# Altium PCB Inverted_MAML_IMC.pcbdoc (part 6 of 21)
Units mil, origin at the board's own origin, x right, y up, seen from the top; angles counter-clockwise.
Board outline 7677.1 x 6771.6 mil, 6 copper layers (Top Layer, Inner1, Inner2, Inner3, Inner4, Bottom Layer), stack 60.7 mil thick; 2732 components, 1531 nets, 7765 pads, 3705 vias.
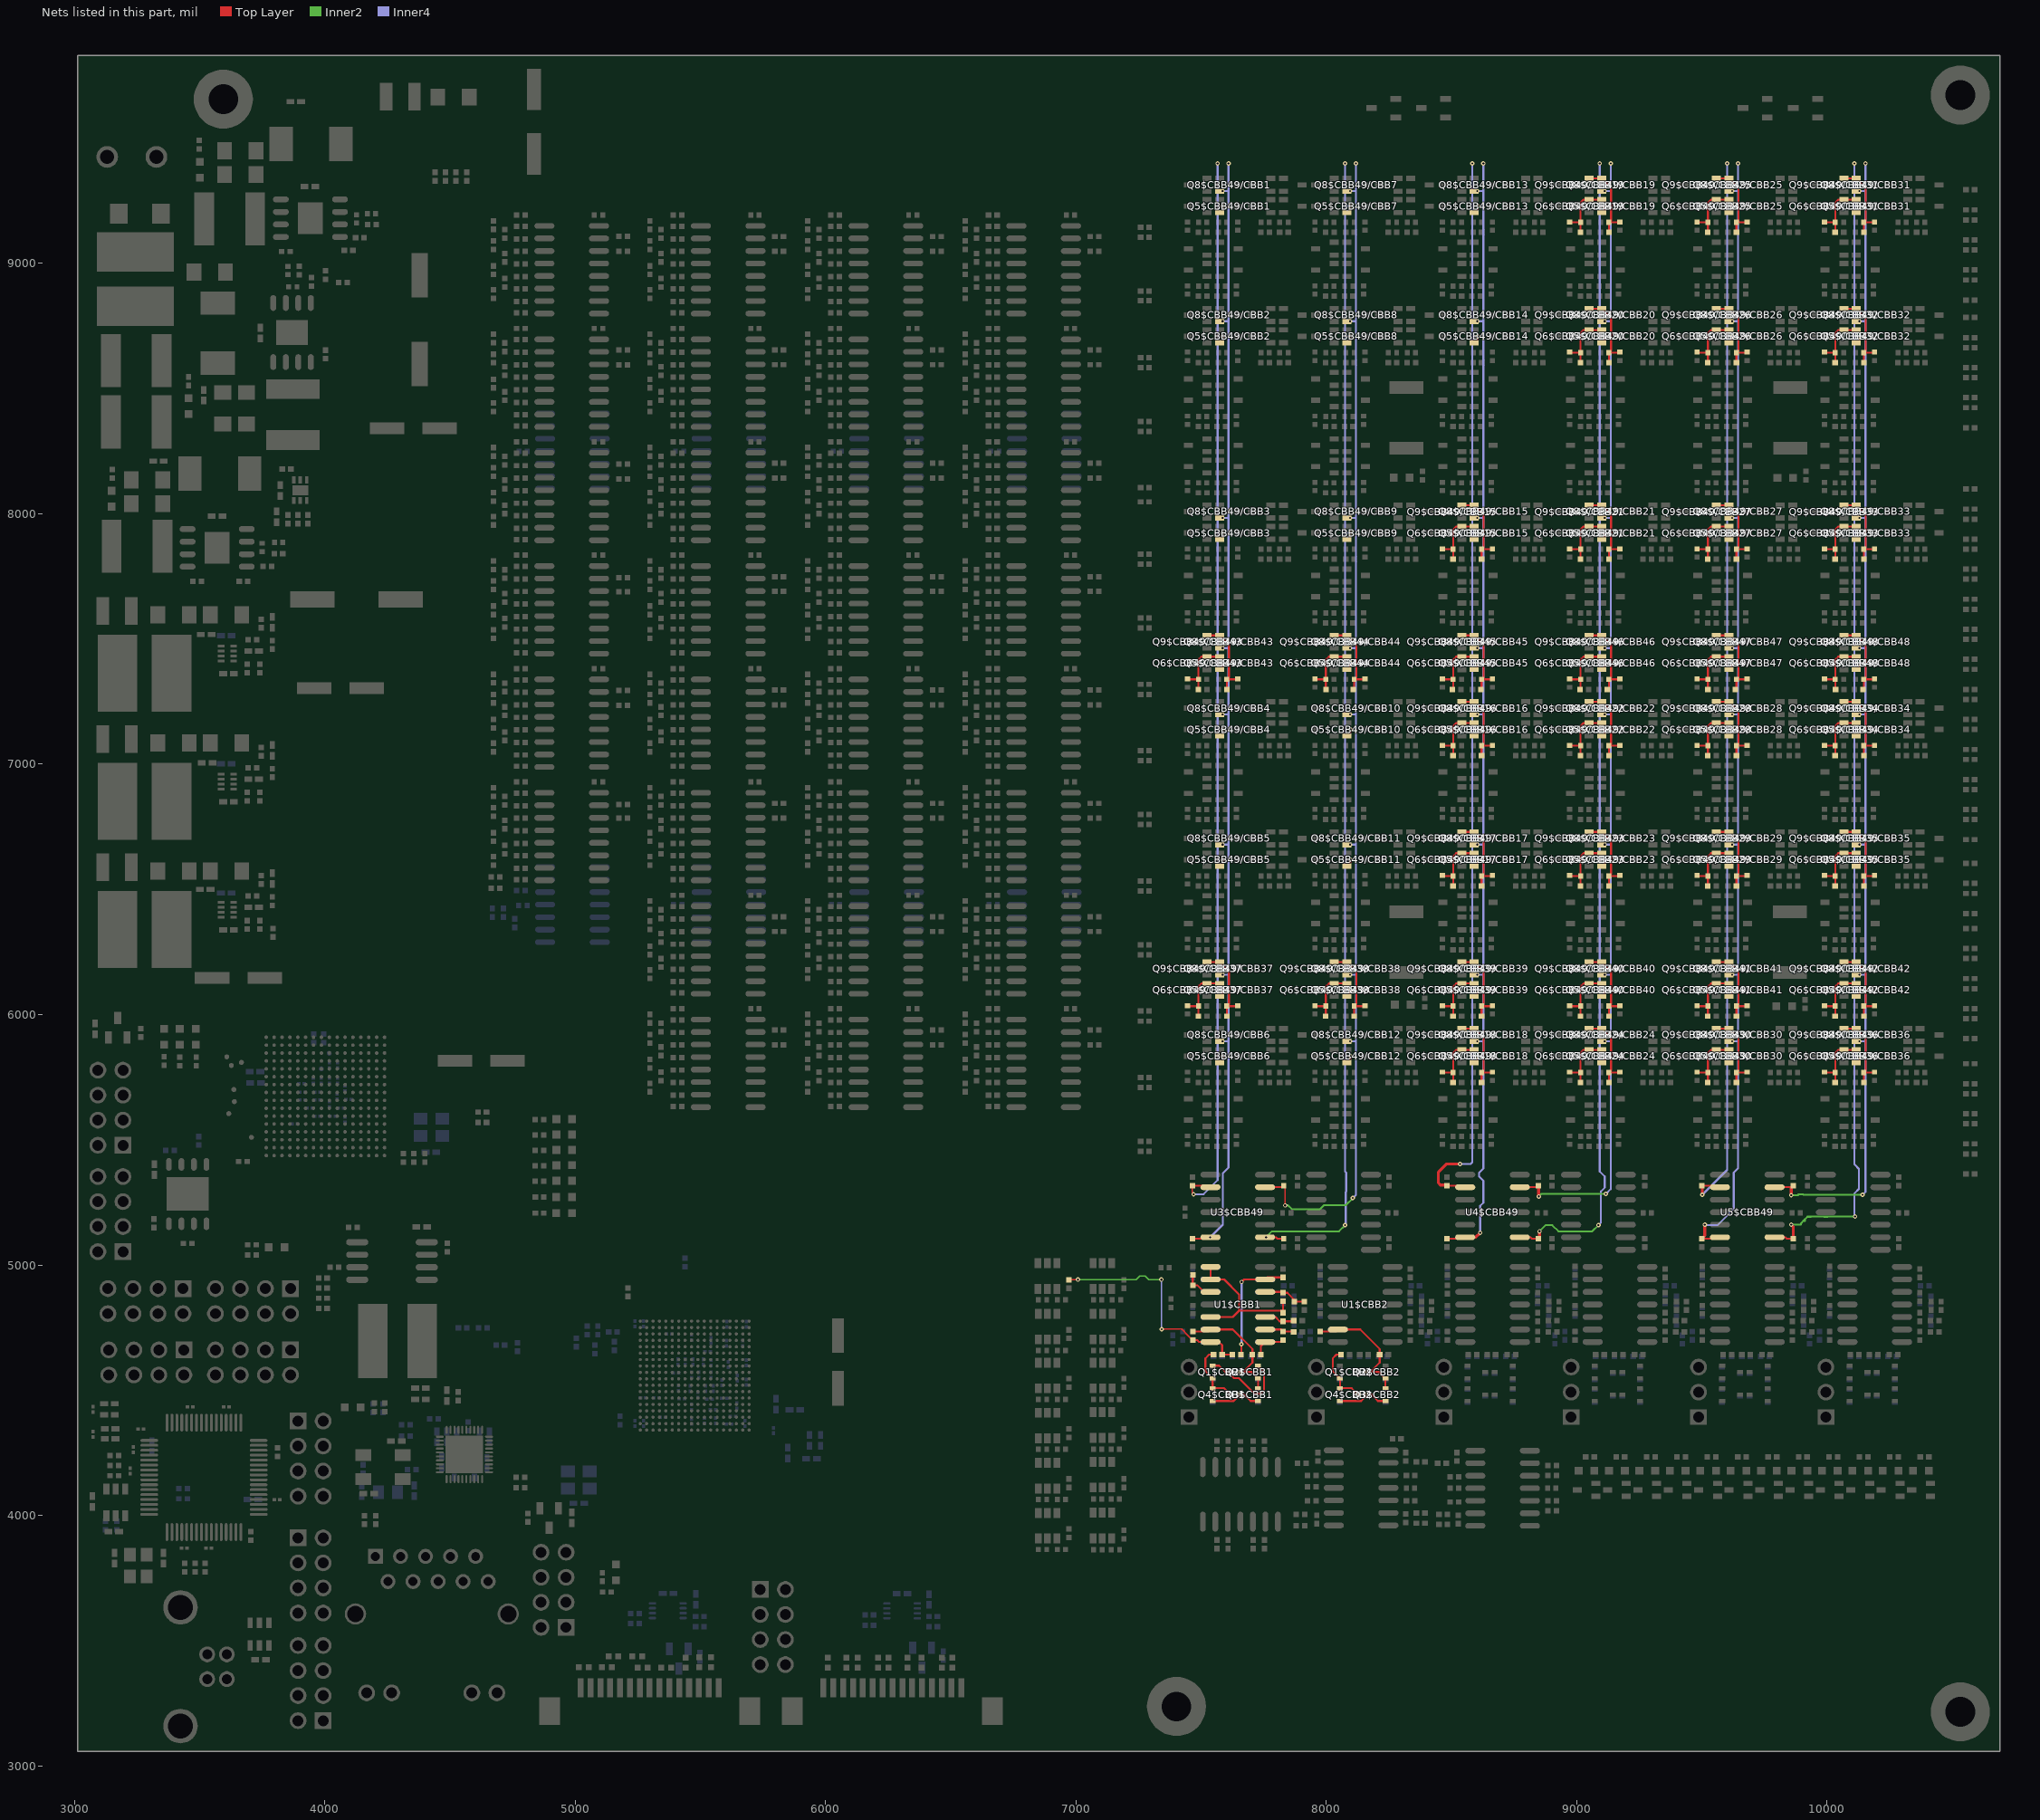
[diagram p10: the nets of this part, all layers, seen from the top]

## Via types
v1: diameter 17.7, hole 7.9, Top Layer to Bottom Layer, 3373 vias
v2: diameter 13.8, hole 7.9, Top Layer to Bottom Layer, 287 vias
v3: diameter 23.6, hole 11.8, Top Layer to Bottom Layer, 45 vias

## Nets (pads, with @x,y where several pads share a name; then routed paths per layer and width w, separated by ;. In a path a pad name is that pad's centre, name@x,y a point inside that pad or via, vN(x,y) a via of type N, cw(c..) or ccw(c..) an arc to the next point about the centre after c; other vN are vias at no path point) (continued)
$1I15\$1I16\$2N1: C1$CBB49/CBB15.2 C2$CBB49/CBB15.2 Q5$CBB49/CBB15.1 Q6$CBB49/CBB15.2 R1$CBB49/CBB15.2 | length 251.9
  Top Layer w7.9: C2$CBB49/CBB15.2@8463.6,7860.2 8465.1,7858.7 C1$CBB49/CBB15.2@8507,7858.7 ; R1$CBB49/CBB15.2@8506.5,7818.7 8507,7819.2 C1$CBB49/CBB15.2@8507,7858.7 ; Q5$CBB49/CBB15.1@8591.2,7949.3 Q6$CBB49/CBB15.2@8541,7949.3 8519.2,7949.3 8507,7937.2 C1$CBB49/CBB15.2@8507,7858.7
$1I15\$1I16\$2N14: C3$CBB49/CBB15.2 C4$CBB49/CBB15.2 Q8$CBB49/CBB15.1 Q9$CBB49/CBB15.2 R2$CBB49/CBB15.2 | length 329.1
  Top Layer w7.9: Q9$CBB49/CBB15.2@8541,8034.3 Q8$CBB49/CBB15.1@8591.2,8034.3 8628.6,7996.9 8628.6,7867.2 C3$CBB49/CBB15.2@8620.1,7858.7 ; R2$CBB49/CBB15.2@8620.6,7818.7 8620.6,7858.2 C3$CBB49/CBB15.2@8620.1,7858.7 ; C4$CBB49/CBB15.2@8663.6,7860.2 8662,7858.7 C3$CBB49/CBB15.2@8620.1,7858.7
$1I15\$1I17\$2N1: C1$CBB49/CBB16.2 C2$CBB49/CBB16.2 Q5$CBB49/CBB16.1 Q6$CBB49/CBB16.2 R1$CBB49/CBB16.2 | length 251.9
  Top Layer w7.9: C2$CBB49/CBB16.2@8463.6,7075.2 8465.1,7073.7 C1$CBB49/CBB16.2@8507,7073.7 ; R1$CBB49/CBB16.2@8506.5,7033.7 8507,7034.2 C1$CBB49/CBB16.2@8507,7073.7 ; Q5$CBB49/CBB16.1@8591.2,7164.3 Q6$CBB49/CBB16.2@8541,7164.3 8519.2,7164.3 8507,7152.2 C1$CBB49/CBB16.2@8507,7073.7
$1I15\$1I17\$2N14: C3$CBB49/CBB16.2 C4$CBB49/CBB16.2 Q8$CBB49/CBB16.1 Q9$CBB49/CBB16.2 R2$CBB49/CBB16.2 | length 329.1
  Top Layer w7.9: Q9$CBB49/CBB16.2@8541,7249.3 Q8$CBB49/CBB16.1@8591.2,7249.3 8628.6,7211.9 8628.6,7082.2 C3$CBB49/CBB16.2@8620.1,7073.7 ; R2$CBB49/CBB16.2@8620.6,7033.7 8620.6,7073.2 C3$CBB49/CBB16.2@8620.1,7073.7 ; C4$CBB49/CBB16.2@8663.6,7075.2 8662,7073.7 C3$CBB49/CBB16.2@8620.1,7073.7
$1I15\$1I18\$2N1: C1$CBB49/CBB17.2 C2$CBB49/CBB17.2 Q5$CBB49/CBB17.1 Q6$CBB49/CBB17.2 R1$CBB49/CBB17.2 | length 251.9
  Top Layer w7.9: C2$CBB49/CBB17.2@8463.6,6555.2 8465.1,6553.7 C1$CBB49/CBB17.2@8507,6553.7 ; R1$CBB49/CBB17.2@8506.5,6513.7 8507,6514.2 C1$CBB49/CBB17.2@8507,6553.7 ; Q5$CBB49/CBB17.1@8591.2,6644.3 Q6$CBB49/CBB17.2@8541,6644.3 8519.2,6644.3 8507,6632.2 C1$CBB49/CBB17.2@8507,6553.7
$1I15\$1I18\$2N14: C3$CBB49/CBB17.2 C4$CBB49/CBB17.2 Q8$CBB49/CBB17.1 Q9$CBB49/CBB17.2 R2$CBB49/CBB17.2 | length 329.1
  Top Layer w7.9: Q9$CBB49/CBB17.2@8541,6729.3 Q8$CBB49/CBB17.1@8591.2,6729.3 8628.6,6691.9 8628.6,6562.2 C3$CBB49/CBB17.2@8620.1,6553.7 ; R2$CBB49/CBB17.2@8620.6,6513.7 8620.6,6553.2 C3$CBB49/CBB17.2@8620.1,6553.7 ; C4$CBB49/CBB17.2@8663.6,6555.2 8662,6553.7 C3$CBB49/CBB17.2@8620.1,6553.7
$1I15\$1I19\$2N1: C1$CBB49/CBB18.2 C2$CBB49/CBB18.2 Q5$CBB49/CBB18.1 Q6$CBB49/CBB18.2 R1$CBB49/CBB18.2 | length 251.9
  Top Layer w7.9: C2$CBB49/CBB18.2@8463.6,5770.2 8465.1,5768.7 C1$CBB49/CBB18.2@8507,5768.7 ; R1$CBB49/CBB18.2@8506.5,5728.7 8507,5729.2 C1$CBB49/CBB18.2@8507,5768.7 ; Q5$CBB49/CBB18.1@8591.2,5859.3 Q6$CBB49/CBB18.2@8541,5859.3 8519.2,5859.3 8507,5847.2 C1$CBB49/CBB18.2@8507,5768.7
$1I15\$1I19\$2N14: C3$CBB49/CBB18.2 C4$CBB49/CBB18.2 Q8$CBB49/CBB18.1 Q9$CBB49/CBB18.2 R2$CBB49/CBB18.2 | length 329.1
  Top Layer w7.9: Q9$CBB49/CBB18.2@8541,5944.3 Q8$CBB49/CBB18.1@8591.2,5944.3 8628.6,5906.9 8628.6,5777.2 C3$CBB49/CBB18.2@8620.1,5768.7 ; R2$CBB49/CBB18.2@8620.6,5728.7 8620.6,5768.2 C3$CBB49/CBB18.2@8620.1,5768.7 ; C4$CBB49/CBB18.2@8663.6,5770.2 8662,5768.7 C3$CBB49/CBB18.2@8620.1,5768.7
$1I15\$1I20\$2N1: C1$CBB49/CBB19.2 C2$CBB49/CBB19.2 Q5$CBB49/CBB19.1 Q6$CBB49/CBB19.2 R1$CBB49/CBB19.2 | length 252
  Top Layer w7.9: C2$CBB49/CBB19.2@8972.3,9165.3 8973.8,9163.7 C1$CBB49/CBB19.2@9015.7,9163.7 ; R1$CBB49/CBB19.2@9015.2,9123.7 9015.7,9124.2 C1$CBB49/CBB19.2@9015.7,9163.7 ; Q5$CBB49/CBB19.1@9099.9,9254.3 Q6$CBB49/CBB19.2@9049.7,9254.3 9027.9,9254.3 9015.7,9242.2 C1$CBB49/CBB19.2@9015.7,9163.7
$1I15\$1I20\$2N14: C3$CBB49/CBB19.2 C4$CBB49/CBB19.2 Q8$CBB49/CBB19.1 Q9$CBB49/CBB19.2 R2$CBB49/CBB19.2 | length 329.2
  Top Layer w7.9: Q9$CBB49/CBB19.2@9049.7,9339.3 Q8$CBB49/CBB19.1@9099.9,9339.3 9137.3,9301.9 9137.3,9172.2 C3$CBB49/CBB19.2@9128.8,9163.7 ; R2$CBB49/CBB19.2@9129.3,9123.7 9129.3,9163.2 C3$CBB49/CBB19.2@9128.8,9163.7 ; C4$CBB49/CBB19.2@9172.3,9165.3 9170.7,9163.7 C3$CBB49/CBB19.2@9128.8,9163.7
$1I15\$1I21\$2N1: C1$CBB49/CBB20.2 C2$CBB49/CBB20.2 Q5$CBB49/CBB20.1 Q6$CBB49/CBB20.2 R1$CBB49/CBB20.2 | length 252
  Top Layer w7.9: C2$CBB49/CBB20.2@8972.3,8645.3 8973.8,8643.7 C1$CBB49/CBB20.2@9015.7,8643.7 ; R1$CBB49/CBB20.2@9015.2,8603.7 9015.7,8604.2 C1$CBB49/CBB20.2@9015.7,8643.7 ; Q5$CBB49/CBB20.1@9099.9,8734.3 Q6$CBB49/CBB20.2@9049.7,8734.3 9027.9,8734.3 9015.7,8722.2 C1$CBB49/CBB20.2@9015.7,8643.7
$1I15\$1I21\$2N14: C3$CBB49/CBB20.2 C4$CBB49/CBB20.2 Q8$CBB49/CBB20.1 Q9$CBB49/CBB20.2 R2$CBB49/CBB20.2 | length 329.2
  Top Layer w7.9: Q9$CBB49/CBB20.2@9049.7,8819.3 Q8$CBB49/CBB20.1@9099.9,8819.3 9137.3,8781.9 9137.3,8652.2 C3$CBB49/CBB20.2@9128.8,8643.7 ; R2$CBB49/CBB20.2@9129.3,8603.7 9129.3,8643.2 C3$CBB49/CBB20.2@9128.8,8643.7 ; C4$CBB49/CBB20.2@9172.3,8645.3 9170.7,8643.7 C3$CBB49/CBB20.2@9128.8,8643.7
$1I15\$1I22\$2N1: C1$CBB49/CBB21.2 C2$CBB49/CBB21.2 Q5$CBB49/CBB21.1 Q6$CBB49/CBB21.2 R1$CBB49/CBB21.2 | length 252
  Top Layer w7.9: C2$CBB49/CBB21.2@8972.3,7860.3 8973.8,7858.7 C1$CBB49/CBB21.2@9015.7,7858.7 ; R1$CBB49/CBB21.2@9015.2,7818.7 9015.7,7819.2 C1$CBB49/CBB21.2@9015.7,7858.7 ; Q5$CBB49/CBB21.1@9099.9,7949.3 Q6$CBB49/CBB21.2@9049.7,7949.3 9027.9,7949.3 9015.7,7937.2 C1$CBB49/CBB21.2@9015.7,7858.7
$1I15\$1I22\$2N14: C3$CBB49/CBB21.2 C4$CBB49/CBB21.2 Q8$CBB49/CBB21.1 Q9$CBB49/CBB21.2 R2$CBB49/CBB21.2 | length 329.2
  Top Layer w7.9: Q9$CBB49/CBB21.2@9049.7,8034.3 Q8$CBB49/CBB21.1@9099.9,8034.3 9137.3,7996.9 9137.3,7867.2 C3$CBB49/CBB21.2@9128.8,7858.7 ; R2$CBB49/CBB21.2@9129.3,7818.7 9129.3,7858.2 C3$CBB49/CBB21.2@9128.8,7858.7 ; C4$CBB49/CBB21.2@9172.3,7860.3 9170.7,7858.7 C3$CBB49/CBB21.2@9128.8,7858.7
$1I15\$1I23\$2N1: C1$CBB49/CBB22.2 C2$CBB49/CBB22.2 Q5$CBB49/CBB22.1 Q6$CBB49/CBB22.2 R1$CBB49/CBB22.2 | length 252
  Top Layer w7.9: C2$CBB49/CBB22.2@8972.3,7075.3 8973.8,7073.7 C1$CBB49/CBB22.2@9015.7,7073.7 ; R1$CBB49/CBB22.2@9015.2,7033.7 9015.7,7034.2 C1$CBB49/CBB22.2@9015.7,7073.7 ; Q5$CBB49/CBB22.1@9099.9,7164.3 Q6$CBB49/CBB22.2@9049.7,7164.3 9027.9,7164.3 9015.7,7152.2 C1$CBB49/CBB22.2@9015.7,7073.7
$1I15\$1I23\$2N14: C3$CBB49/CBB22.2 C4$CBB49/CBB22.2 Q8$CBB49/CBB22.1 Q9$CBB49/CBB22.2 R2$CBB49/CBB22.2 | length 329.2
  Top Layer w7.9: Q9$CBB49/CBB22.2@9049.7,7249.3 Q8$CBB49/CBB22.1@9099.9,7249.3 9137.3,7211.9 9137.3,7082.2 C3$CBB49/CBB22.2@9128.8,7073.7 ; R2$CBB49/CBB22.2@9129.3,7033.7 9129.3,7073.2 C3$CBB49/CBB22.2@9128.8,7073.7 ; C4$CBB49/CBB22.2@9172.3,7075.3 9170.7,7073.7 C3$CBB49/CBB22.2@9128.8,7073.7
$1I15\$1I24\$2N1: C1$CBB49/CBB23.2 C2$CBB49/CBB23.2 Q5$CBB49/CBB23.1 Q6$CBB49/CBB23.2 R1$CBB49/CBB23.2 | length 252
  Top Layer w7.9: C2$CBB49/CBB23.2@8972.3,6555.3 8973.8,6553.7 C1$CBB49/CBB23.2@9015.7,6553.7 ; R1$CBB49/CBB23.2@9015.2,6513.7 9015.7,6514.2 C1$CBB49/CBB23.2@9015.7,6553.7 ; Q5$CBB49/CBB23.1@9099.9,6644.3 Q6$CBB49/CBB23.2@9049.7,6644.3 9027.9,6644.3 9015.7,6632.2 C1$CBB49/CBB23.2@9015.7,6553.7
$1I15\$1I24\$2N14: C3$CBB49/CBB23.2 C4$CBB49/CBB23.2 Q8$CBB49/CBB23.1 Q9$CBB49/CBB23.2 R2$CBB49/CBB23.2 | length 329.2
  Top Layer w7.9: Q9$CBB49/CBB23.2@9049.7,6729.3 Q8$CBB49/CBB23.1@9099.9,6729.3 9137.3,6691.9 9137.3,6562.2 C3$CBB49/CBB23.2@9128.8,6553.7 ; R2$CBB49/CBB23.2@9129.3,6513.7 9129.3,6553.2 C3$CBB49/CBB23.2@9128.8,6553.7 ; C4$CBB49/CBB23.2@9172.3,6555.3 9170.7,6553.7 C3$CBB49/CBB23.2@9128.8,6553.7
$1I15\$1I25\$2N1: C1$CBB49/CBB24.2 C2$CBB49/CBB24.2 Q5$CBB49/CBB24.1 Q6$CBB49/CBB24.2 R1$CBB49/CBB24.2 | length 252
  Top Layer w7.9: C2$CBB49/CBB24.2@8972.3,5770.3 8973.8,5768.7 C1$CBB49/CBB24.2@9015.7,5768.7 ; R1$CBB49/CBB24.2@9015.2,5728.7 9015.7,5729.2 C1$CBB49/CBB24.2@9015.7,5768.7 ; Q5$CBB49/CBB24.1@9099.9,5859.3 Q6$CBB49/CBB24.2@9049.7,5859.3 9027.9,5859.3 9015.7,5847.2 C1$CBB49/CBB24.2@9015.7,5768.7
$1I15\$1I25\$2N14: C3$CBB49/CBB24.2 C4$CBB49/CBB24.2 Q8$CBB49/CBB24.1 Q9$CBB49/CBB24.2 R2$CBB49/CBB24.2 | length 329.2
  Top Layer w7.9: Q9$CBB49/CBB24.2@9049.7,5944.3 Q8$CBB49/CBB24.1@9099.9,5944.3 9137.3,5906.9 9137.3,5777.2 C3$CBB49/CBB24.2@9128.8,5768.7 ; R2$CBB49/CBB24.2@9129.3,5728.7 9129.3,5768.2 C3$CBB49/CBB24.2@9128.8,5768.7 ; C4$CBB49/CBB24.2@9172.3,5770.3 9170.7,5768.7 C3$CBB49/CBB24.2@9128.8,5768.7
$1I15\$1I26\$2N1: C1$CBB49/CBB25.2 C2$CBB49/CBB25.2 Q5$CBB49/CBB25.1 Q6$CBB49/CBB25.2 R1$CBB49/CBB25.2 | length 252
  Top Layer w7.9: C2$CBB49/CBB25.2@9481,9165.3 9482.5,9163.7 C1$CBB49/CBB25.2@9524.4,9163.7 ; R1$CBB49/CBB25.2@9523.9,9123.7 9524.4,9124.2 C1$CBB49/CBB25.2@9524.4,9163.7 ; Q5$CBB49/CBB25.1@9608.6,9254.3 Q6$CBB49/CBB25.2@9558.4,9254.3 9536.6,9254.3 9524.4,9242.2 C1$CBB49/CBB25.2@9524.4,9163.7
$1I15\$1I26\$2N14: C3$CBB49/CBB25.2 C4$CBB49/CBB25.2 Q8$CBB49/CBB25.1 Q9$CBB49/CBB25.2 R2$CBB49/CBB25.2 | length 329.2
  Top Layer w7.9: Q9$CBB49/CBB25.2@9558.4,9339.3 Q8$CBB49/CBB25.1@9608.6,9339.3 9646,9301.9 9646,9172.2 C3$CBB49/CBB25.2@9637.5,9163.7 ; R2$CBB49/CBB25.2@9638,9123.7 9638,9163.2 C3$CBB49/CBB25.2@9637.5,9163.7 ; C4$CBB49/CBB25.2@9681,9165.3 9679.4,9163.7 C3$CBB49/CBB25.2@9637.5,9163.7
$1I15\$1I27\$2N1: C1$CBB49/CBB26.2 C2$CBB49/CBB26.2 Q5$CBB49/CBB26.1 Q6$CBB49/CBB26.2 R1$CBB49/CBB26.2 | length 252
  Top Layer w7.9: C2$CBB49/CBB26.2@9481,8645.3 9482.5,8643.7 C1$CBB49/CBB26.2@9524.4,8643.7 ; R1$CBB49/CBB26.2@9523.9,8603.7 9524.4,8604.2 C1$CBB49/CBB26.2@9524.4,8643.7 ; Q5$CBB49/CBB26.1@9608.6,8734.3 Q6$CBB49/CBB26.2@9558.4,8734.3 9536.6,8734.3 9524.4,8722.2 C1$CBB49/CBB26.2@9524.4,8643.7
$1I15\$1I27\$2N14: C3$CBB49/CBB26.2 C4$CBB49/CBB26.2 Q8$CBB49/CBB26.1 Q9$CBB49/CBB26.2 R2$CBB49/CBB26.2 | length 329.2
  Top Layer w7.9: Q9$CBB49/CBB26.2@9558.4,8819.3 Q8$CBB49/CBB26.1@9608.6,8819.3 9646,8781.9 9646,8652.2 C3$CBB49/CBB26.2@9637.5,8643.7 ; R2$CBB49/CBB26.2@9638,8603.7 9638,8643.2 C3$CBB49/CBB26.2@9637.5,8643.7 ; C4$CBB49/CBB26.2@9681,8645.3 9679.4,8643.7 C3$CBB49/CBB26.2@9637.5,8643.7
$1I15\$1I28\$2N1: C1$CBB49/CBB27.2 C2$CBB49/CBB27.2 Q5$CBB49/CBB27.1 Q6$CBB49/CBB27.2 R1$CBB49/CBB27.2 | length 252
  Top Layer w7.9: C2$CBB49/CBB27.2@9481,7860.3 9482.5,7858.7 C1$CBB49/CBB27.2@9524.4,7858.7 ; R1$CBB49/CBB27.2@9523.9,7818.7 9524.4,7819.2 C1$CBB49/CBB27.2@9524.4,7858.7 ; Q5$CBB49/CBB27.1@9608.6,7949.3 Q6$CBB49/CBB27.2@9558.4,7949.3 9536.6,7949.3 9524.4,7937.2 C1$CBB49/CBB27.2@9524.4,7858.7
$1I15\$1I28\$2N14: C3$CBB49/CBB27.2 C4$CBB49/CBB27.2 Q8$CBB49/CBB27.1 Q9$CBB49/CBB27.2 R2$CBB49/CBB27.2 | length 329.2
  Top Layer w7.9: Q9$CBB49/CBB27.2@9558.4,8034.3 Q8$CBB49/CBB27.1@9608.6,8034.3 9646,7996.9 9646,7867.2 C3$CBB49/CBB27.2@9637.5,7858.7 ; R2$CBB49/CBB27.2@9638,7818.7 9638,7858.2 C3$CBB49/CBB27.2@9637.5,7858.7 ; C4$CBB49/CBB27.2@9681,7860.3 9679.4,7858.7 C3$CBB49/CBB27.2@9637.5,7858.7
$1I15\$1I29\$2N1: C1$CBB49/CBB28.2 C2$CBB49/CBB28.2 Q5$CBB49/CBB28.1 Q6$CBB49/CBB28.2 R1$CBB49/CBB28.2 | length 252
  Top Layer w7.9: C2$CBB49/CBB28.2@9481,7075.3 9482.5,7073.7 C1$CBB49/CBB28.2@9524.4,7073.7 ; R1$CBB49/CBB28.2@9523.9,7033.7 9524.4,7034.2 C1$CBB49/CBB28.2@9524.4,7073.7 ; Q5$CBB49/CBB28.1@9608.6,7164.3 Q6$CBB49/CBB28.2@9558.4,7164.3 9536.6,7164.3 9524.4,7152.2 C1$CBB49/CBB28.2@9524.4,7073.7
$1I15\$1I29\$2N14: C3$CBB49/CBB28.2 C4$CBB49/CBB28.2 Q8$CBB49/CBB28.1 Q9$CBB49/CBB28.2 R2$CBB49/CBB28.2 | length 329.2
  Top Layer w7.9: Q9$CBB49/CBB28.2@9558.4,7249.3 Q8$CBB49/CBB28.1@9608.6,7249.3 9646,7211.9 9646,7082.2 C3$CBB49/CBB28.2@9637.5,7073.7 ; R2$CBB49/CBB28.2@9638,7033.7 9638,7073.2 C3$CBB49/CBB28.2@9637.5,7073.7 ; C4$CBB49/CBB28.2@9681,7075.3 9679.4,7073.7 C3$CBB49/CBB28.2@9637.5,7073.7
$1I15\$1I30\$2N1: C1$CBB49/CBB29.2 C2$CBB49/CBB29.2 Q5$CBB49/CBB29.1 Q6$CBB49/CBB29.2 R1$CBB49/CBB29.2 | length 252
  Top Layer w7.9: C2$CBB49/CBB29.2@9481,6555.3 9482.5,6553.7 C1$CBB49/CBB29.2@9524.4,6553.7 ; R1$CBB49/CBB29.2@9523.9,6513.7 9524.4,6514.2 C1$CBB49/CBB29.2@9524.4,6553.7 ; Q5$CBB49/CBB29.1@9608.6,6644.3 Q6$CBB49/CBB29.2@9558.4,6644.3 9536.6,6644.3 9524.4,6632.2 C1$CBB49/CBB29.2@9524.4,6553.7
$1I15\$1I30\$2N14: C3$CBB49/CBB29.2 C4$CBB49/CBB29.2 Q8$CBB49/CBB29.1 Q9$CBB49/CBB29.2 R2$CBB49/CBB29.2 | length 329.2
  Top Layer w7.9: Q9$CBB49/CBB29.2@9558.4,6729.3 Q8$CBB49/CBB29.1@9608.6,6729.3 9646,6691.9 9646,6562.2 C3$CBB49/CBB29.2@9637.5,6553.7 ; R2$CBB49/CBB29.2@9638,6513.7 9638,6553.2 C3$CBB49/CBB29.2@9637.5,6553.7 ; C4$CBB49/CBB29.2@9681,6555.3 9679.4,6553.7 C3$CBB49/CBB29.2@9637.5,6553.7
$1I15\$1I31\$2N1: C1$CBB49/CBB30.2 C2$CBB49/CBB30.2 Q5$CBB49/CBB30.1 Q6$CBB49/CBB30.2 R1$CBB49/CBB30.2 | length 252
  Top Layer w7.9: C2$CBB49/CBB30.2@9481,5770.3 9482.5,5768.7 C1$CBB49/CBB30.2@9524.4,5768.7 ; R1$CBB49/CBB30.2@9523.9,5728.7 9524.4,5729.2 C1$CBB49/CBB30.2@9524.4,5768.7 ; Q5$CBB49/CBB30.1@9608.6,5859.3 Q6$CBB49/CBB30.2@9558.4,5859.3 9536.6,5859.3 9524.4,5847.2 C1$CBB49/CBB30.2@9524.4,5768.7
$1I15\$1I31\$2N14: C3$CBB49/CBB30.2 C4$CBB49/CBB30.2 Q8$CBB49/CBB30.1 Q9$CBB49/CBB30.2 R2$CBB49/CBB30.2 | length 329.2
  Top Layer w7.9: Q9$CBB49/CBB30.2@9558.4,5944.3 Q8$CBB49/CBB30.1@9608.6,5944.3 9646,5906.9 9646,5777.2 C3$CBB49/CBB30.2@9637.5,5768.7 ; R2$CBB49/CBB30.2@9638,5728.7 9638,5768.2 C3$CBB49/CBB30.2@9637.5,5768.7 ; C4$CBB49/CBB30.2@9681,5770.3 9679.4,5768.7 C3$CBB49/CBB30.2@9637.5,5768.7
$1I15\$1I32\$2N1: C1$CBB49/CBB31.2 C2$CBB49/CBB31.2 Q5$CBB49/CBB31.1 Q6$CBB49/CBB31.2 R1$CBB49/CBB31.2 | length 252
  Top Layer w7.9: C2$CBB49/CBB31.2@9989.7,9165.3 9991.2,9163.7 C1$CBB49/CBB31.2@10033.1,9163.7 ; R1$CBB49/CBB31.2@10032.6,9123.7 10033.1,9124.2 C1$CBB49/CBB31.2@10033.1,9163.7 ; Q5$CBB49/CBB31.1@10117.3,9254.3 Q6$CBB49/CBB31.2@10067.1,9254.3 10045.3,9254.3 10033.1,9242.2 C1$CBB49/CBB31.2@10033.1,9163.7
$1I15\$1I32\$2N14: C3$CBB49/CBB31.2 C4$CBB49/CBB31.2 Q8$CBB49/CBB31.1 Q9$CBB49/CBB31.2 R2$CBB49/CBB31.2 | length 329.2
  Top Layer w7.9: Q9$CBB49/CBB31.2@10067.1,9339.3 Q8$CBB49/CBB31.1@10117.3,9339.3 10154.7,9301.9 10154.7,9172.2 C3$CBB49/CBB31.2@10146.2,9163.7 ; R2$CBB49/CBB31.2@10146.7,9123.7 10146.7,9163.2 C3$CBB49/CBB31.2@10146.2,9163.7 ; C4$CBB49/CBB31.2@10189.7,9165.3 10188.1,9163.7 C3$CBB49/CBB31.2@10146.2,9163.7
$1I15\$1I33\$2N1: C1$CBB49/CBB32.2 C2$CBB49/CBB32.2 Q5$CBB49/CBB32.1 Q6$CBB49/CBB32.2 R1$CBB49/CBB32.2 | length 252
  Top Layer w7.9: C2$CBB49/CBB32.2@9989.7,8645.3 9991.2,8643.7 C1$CBB49/CBB32.2@10033.1,8643.7 ; R1$CBB49/CBB32.2@10032.6,8603.7 10033.1,8604.2 C1$CBB49/CBB32.2@10033.1,8643.7 ; Q5$CBB49/CBB32.1@10117.3,8734.3 Q6$CBB49/CBB32.2@10067.1,8734.3 10045.3,8734.3 10033.1,8722.2 C1$CBB49/CBB32.2@10033.1,8643.7
$1I15\$1I33\$2N14: C3$CBB49/CBB32.2 C4$CBB49/CBB32.2 Q8$CBB49/CBB32.1 Q9$CBB49/CBB32.2 R2$CBB49/CBB32.2 | length 329.2
  Top Layer w7.9: Q9$CBB49/CBB32.2@10067.1,8819.3 Q8$CBB49/CBB32.1@10117.3,8819.3 10154.7,8781.9 10154.7,8652.2 C3$CBB49/CBB32.2@10146.2,8643.7 ; R2$CBB49/CBB32.2@10146.7,8603.7 10146.7,8643.2 C3$CBB49/CBB32.2@10146.2,8643.7 ; C4$CBB49/CBB32.2@10189.7,8645.3 10188.1,8643.7 C3$CBB49/CBB32.2@10146.2,8643.7
$1I15\$1I34\$2N1: C1$CBB49/CBB33.2 C2$CBB49/CBB33.2 Q5$CBB49/CBB33.1 Q6$CBB49/CBB33.2 R1$CBB49/CBB33.2 | length 252
  Top Layer w7.9: C2$CBB49/CBB33.2@9989.7,7860.3 9991.2,7858.7 C1$CBB49/CBB33.2@10033.1,7858.7 ; R1$CBB49/CBB33.2@10032.6,7818.7 10033.1,7819.2 C1$CBB49/CBB33.2@10033.1,7858.7 ; Q5$CBB49/CBB33.1@10117.3,7949.3 Q6$CBB49/CBB33.2@10067.1,7949.3 10045.3,7949.3 10033.1,7937.2 C1$CBB49/CBB33.2@10033.1,7858.7
$1I15\$1I34\$2N14: C3$CBB49/CBB33.2 C4$CBB49/CBB33.2 Q8$CBB49/CBB33.1 Q9$CBB49/CBB33.2 R2$CBB49/CBB33.2 | length 329.2
  Top Layer w7.9: Q9$CBB49/CBB33.2@10067.1,8034.3 Q8$CBB49/CBB33.1@10117.3,8034.3 10154.7,7996.9 10154.7,7867.2 C3$CBB49/CBB33.2@10146.2,7858.7 ; R2$CBB49/CBB33.2@10146.7,7818.7 10146.7,7858.2 C3$CBB49/CBB33.2@10146.2,7858.7 ; C4$CBB49/CBB33.2@10189.7,7860.3 10188.1,7858.7 C3$CBB49/CBB33.2@10146.2,7858.7
$1I15\$1I35\$2N1: C1$CBB49/CBB34.2 C2$CBB49/CBB34.2 Q5$CBB49/CBB34.1 Q6$CBB49/CBB34.2 R1$CBB49/CBB34.2 | length 252
  Top Layer w7.9: C2$CBB49/CBB34.2@9989.7,7075.3 9991.2,7073.7 C1$CBB49/CBB34.2@10033.1,7073.7 ; R1$CBB49/CBB34.2@10032.6,7033.7 10033.1,7034.2 C1$CBB49/CBB34.2@10033.1,7073.7 ; Q5$CBB49/CBB34.1@10117.3,7164.3 Q6$CBB49/CBB34.2@10067.1,7164.3 10045.3,7164.3 10033.1,7152.2 C1$CBB49/CBB34.2@10033.1,7073.7
$1I15\$1I35\$2N14: C3$CBB49/CBB34.2 C4$CBB49/CBB34.2 Q8$CBB49/CBB34.1 Q9$CBB49/CBB34.2 R2$CBB49/CBB34.2 | length 329.2
  Top Layer w7.9: Q9$CBB49/CBB34.2@10067.1,7249.3 Q8$CBB49/CBB34.1@10117.3,7249.3 10154.7,7211.9 10154.7,7082.2 C3$CBB49/CBB34.2@10146.2,7073.7 ; R2$CBB49/CBB34.2@10146.7,7033.7 10146.7,7073.2 C3$CBB49/CBB34.2@10146.2,7073.7 ; C4$CBB49/CBB34.2@10189.7,7075.3 10188.1,7073.7 C3$CBB49/CBB34.2@10146.2,7073.7
$1I15\$1I36\$2N1: C1$CBB49/CBB35.2 C2$CBB49/CBB35.2 Q5$CBB49/CBB35.1 Q6$CBB49/CBB35.2 R1$CBB49/CBB35.2 | length 252
  Top Layer w7.9: C2$CBB49/CBB35.2@9989.7,6555.3 9991.2,6553.7 C1$CBB49/CBB35.2@10033.1,6553.7 ; R1$CBB49/CBB35.2@10032.6,6513.7 10033.1,6514.2 C1$CBB49/CBB35.2@10033.1,6553.7 ; Q5$CBB49/CBB35.1@10117.3,6644.3 Q6$CBB49/CBB35.2@10067.1,6644.3 10045.3,6644.3 10033.1,6632.2 C1$CBB49/CBB35.2@10033.1,6553.7
$1I15\$1I36\$2N14: C3$CBB49/CBB35.2 C4$CBB49/CBB35.2 Q8$CBB49/CBB35.1 Q9$CBB49/CBB35.2 R2$CBB49/CBB35.2 | length 329.2
  Top Layer w7.9: Q9$CBB49/CBB35.2@10067.1,6729.3 Q8$CBB49/CBB35.1@10117.3,6729.3 10154.7,6691.9 10154.7,6562.2 C3$CBB49/CBB35.2@10146.2,6553.7 ; R2$CBB49/CBB35.2@10146.7,6513.7 10146.7,6553.2 C3$CBB49/CBB35.2@10146.2,6553.7 ; C4$CBB49/CBB35.2@10189.7,6555.3 10188.1,6553.7 C3$CBB49/CBB35.2@10146.2,6553.7
$1I15\$1I37\$2N1: C1$CBB49/CBB36.2 C2$CBB49/CBB36.2 Q5$CBB49/CBB36.1 Q6$CBB49/CBB36.2 R1$CBB49/CBB36.2 | length 252
  Top Layer w7.9: C2$CBB49/CBB36.2@9989.7,5770.3 9991.2,5768.7 C1$CBB49/CBB36.2@10033.1,5768.7 ; R1$CBB49/CBB36.2@10032.6,5728.7 10033.1,5729.2 C1$CBB49/CBB36.2@10033.1,5768.7 ; Q5$CBB49/CBB36.1@10117.3,5859.3 Q6$CBB49/CBB36.2@10067.1,5859.3 10045.3,5859.3 10033.1,5847.2 C1$CBB49/CBB36.2@10033.1,5768.7
$1I15\$1I37\$2N14: C3$CBB49/CBB36.2 C4$CBB49/CBB36.2 Q8$CBB49/CBB36.1 Q9$CBB49/CBB36.2 R2$CBB49/CBB36.2 | length 329.2
  Top Layer w7.9: Q9$CBB49/CBB36.2@10067.1,5944.3 Q8$CBB49/CBB36.1@10117.3,5944.3 10154.7,5906.9 10154.7,5777.2 C3$CBB49/CBB36.2@10146.2,5768.7 ; R2$CBB49/CBB36.2@10146.7,5728.7 10146.7,5768.2 C3$CBB49/CBB36.2@10146.2,5768.7 ; C4$CBB49/CBB36.2@10189.7,5770.3 10188.1,5768.7 C3$CBB49/CBB36.2@10146.2,5768.7
$1I15\$1I38\$2N1: C1$CBB49/CBB37.2 C2$CBB49/CBB37.2 Q5$CBB49/CBB37.1 Q6$CBB49/CBB37.2 R1$CBB49/CBB37.2 | length 252
  Top Layer w7.9: C2$CBB49/CBB37.2@7446.2,6035.3 7447.7,6033.7 C1$CBB49/CBB37.2@7489.6,6033.7 ; R1$CBB49/CBB37.2@7489.1,5993.7 7489.6,5994.2 C1$CBB49/CBB37.2@7489.6,6033.7 ; Q5$CBB49/CBB37.1@7573.8,6124.3 Q6$CBB49/CBB37.2@7523.6,6124.3 7501.8,6124.3 7489.6,6112.2 C1$CBB49/CBB37.2@7489.6,6033.7
$1I15\$1I38\$2N14: C3$CBB49/CBB37.2 C4$CBB49/CBB37.2 Q8$CBB49/CBB37.1 Q9$CBB49/CBB37.2 R2$CBB49/CBB37.2 | length 329.2
  Top Layer w7.9: Q9$CBB49/CBB37.2@7523.6,6209.3 Q8$CBB49/CBB37.1@7573.8,6209.3 7611.2,6171.9 7611.2,6042.2 C3$CBB49/CBB37.2@7602.7,6033.7 ; R2$CBB49/CBB37.2@7603.2,5993.7 7603.2,6033.2 C3$CBB49/CBB37.2@7602.7,6033.7 ; C4$CBB49/CBB37.2@7646.2,6035.3 7644.6,6033.7 C3$CBB49/CBB37.2@7602.7,6033.7
$1I15\$1I39\$2N1: C1$CBB49/CBB38.2 C2$CBB49/CBB38.2 Q5$CBB49/CBB38.1 Q6$CBB49/CBB38.2 R1$CBB49/CBB38.2 | length 252
  Top Layer w7.9: C2$CBB49/CBB38.2@7954.9,6035.3 7956.4,6033.7 C1$CBB49/CBB38.2@7998.3,6033.7 ; R1$CBB49/CBB38.2@7997.8,5993.7 7998.3,5994.2 C1$CBB49/CBB38.2@7998.3,6033.7 ; Q5$CBB49/CBB38.1@8082.5,6124.3 Q6$CBB49/CBB38.2@8032.3,6124.3 8010.5,6124.3 7998.3,6112.2 C1$CBB49/CBB38.2@7998.3,6033.7
$1I15\$1I39\$2N14: C3$CBB49/CBB38.2 C4$CBB49/CBB38.2 Q8$CBB49/CBB38.1 Q9$CBB49/CBB38.2 R2$CBB49/CBB38.2 | length 329.2
  Top Layer w7.9: Q9$CBB49/CBB38.2@8032.3,6209.3 Q8$CBB49/CBB38.1@8082.5,6209.3 8119.9,6171.9 8119.9,6042.2 C3$CBB49/CBB38.2@8111.4,6033.7 ; R2$CBB49/CBB38.2@8111.9,5993.7 8111.9,6033.2 C3$CBB49/CBB38.2@8111.4,6033.7 ; C4$CBB49/CBB38.2@8154.9,6035.3 8153.3,6033.7 C3$CBB49/CBB38.2@8111.4,6033.7
$1I15\$1I40\$2N1: C1$CBB49/CBB39.2 C2$CBB49/CBB39.2 Q5$CBB49/CBB39.1 Q6$CBB49/CBB39.2 R1$CBB49/CBB39.2 | length 252
  Top Layer w7.9: C2$CBB49/CBB39.2@8463.6,6035.3 8465.1,6033.7 C1$CBB49/CBB39.2@8507,6033.7 ; R1$CBB49/CBB39.2@8506.5,5993.7 8507,5994.2 C1$CBB49/CBB39.2@8507,6033.7 ; Q5$CBB49/CBB39.1@8591.2,6124.3 Q6$CBB49/CBB39.2@8541,6124.3 8519.2,6124.3 8507,6112.2 C1$CBB49/CBB39.2@8507,6033.7
$1I15\$1I40\$2N14: C3$CBB49/CBB39.2 C4$CBB49/CBB39.2 Q8$CBB49/CBB39.1 Q9$CBB49/CBB39.2 R2$CBB49/CBB39.2 | length 329.2
  Top Layer w7.9: Q9$CBB49/CBB39.2@8541,6209.3 Q8$CBB49/CBB39.1@8591.2,6209.3 8628.6,6171.9 8628.6,6042.2 C3$CBB49/CBB39.2@8620.1,6033.7 ; R2$CBB49/CBB39.2@8620.6,5993.7 8620.6,6033.2 C3$CBB49/CBB39.2@8620.1,6033.7 ; C4$CBB49/CBB39.2@8663.6,6035.3 8662,6033.7 C3$CBB49/CBB39.2@8620.1,6033.7
$1I15\$1I41\$2N1: C1$CBB49/CBB40.2 C2$CBB49/CBB40.2 Q5$CBB49/CBB40.1 Q6$CBB49/CBB40.2 R1$CBB49/CBB40.2 | length 252
  Top Layer w7.9: C2$CBB49/CBB40.2@8972.3,6035.3 8973.8,6033.7 C1$CBB49/CBB40.2@9015.7,6033.7 ; R1$CBB49/CBB40.2@9015.2,5993.7 9015.7,5994.2 C1$CBB49/CBB40.2@9015.7,6033.7 ; Q5$CBB49/CBB40.1@9099.9,6124.3 Q6$CBB49/CBB40.2@9049.7,6124.3 9027.9,6124.3 9015.7,6112.2 C1$CBB49/CBB40.2@9015.7,6033.7
$1I15\$1I41\$2N14: C3$CBB49/CBB40.2 C4$CBB49/CBB40.2 Q8$CBB49/CBB40.1 Q9$CBB49/CBB40.2 R2$CBB49/CBB40.2 | length 329.2
  Top Layer w7.9: Q9$CBB49/CBB40.2@9049.7,6209.3 Q8$CBB49/CBB40.1@9099.9,6209.3 9137.3,6171.9 9137.3,6042.2 C3$CBB49/CBB40.2@9128.8,6033.7 ; R2$CBB49/CBB40.2@9129.3,5993.7 9129.3,6033.2 C3$CBB49/CBB40.2@9128.8,6033.7 ; C4$CBB49/CBB40.2@9172.3,6035.3 9170.7,6033.7 C3$CBB49/CBB40.2@9128.8,6033.7
$1I15\$1I42\$2N1: C1$CBB49/CBB41.2 C2$CBB49/CBB41.2 Q5$CBB49/CBB41.1 Q6$CBB49/CBB41.2 R1$CBB49/CBB41.2 | length 252
  Top Layer w7.9: C2$CBB49/CBB41.2@9481,6035.3 9482.5,6033.7 C1$CBB49/CBB41.2@9524.4,6033.7 ; R1$CBB49/CBB41.2@9523.9,5993.7 9524.4,5994.2 C1$CBB49/CBB41.2@9524.4,6033.7 ; Q5$CBB49/CBB41.1@9608.6,6124.3 Q6$CBB49/CBB41.2@9558.4,6124.3 9536.6,6124.3 9524.4,6112.2 C1$CBB49/CBB41.2@9524.4,6033.7
$1I15\$1I42\$2N14: C3$CBB49/CBB41.2 C4$CBB49/CBB41.2 Q8$CBB49/CBB41.1 Q9$CBB49/CBB41.2 R2$CBB49/CBB41.2 | length 329.2
  Top Layer w7.9: Q9$CBB49/CBB41.2@9558.4,6209.3 Q8$CBB49/CBB41.1@9608.6,6209.3 9646,6171.9 9646,6042.2 C3$CBB49/CBB41.2@9637.5,6033.7 ; R2$CBB49/CBB41.2@9638,5993.7 9638,6033.2 C3$CBB49/CBB41.2@9637.5,6033.7 ; C4$CBB49/CBB41.2@9681,6035.3 9679.4,6033.7 C3$CBB49/CBB41.2@9637.5,6033.7
$1I15\$1I43\$2N1: C1$CBB49/CBB42.2 C2$CBB49/CBB42.2 Q5$CBB49/CBB42.1 Q6$CBB49/CBB42.2 R1$CBB49/CBB42.2 | length 252
  Top Layer w7.9: C2$CBB49/CBB42.2@9989.7,6035.3 9991.2,6033.7 C1$CBB49/CBB42.2@10033.1,6033.7 ; R1$CBB49/CBB42.2@10032.6,5993.7 10033.1,5994.2 C1$CBB49/CBB42.2@10033.1,6033.7 ; Q5$CBB49/CBB42.1@10117.3,6124.3 Q6$CBB49/CBB42.2@10067.1,6124.3 10045.3,6124.3 10033.1,6112.2 C1$CBB49/CBB42.2@10033.1,6033.7
$1I15\$1I43\$2N14: C3$CBB49/CBB42.2 C4$CBB49/CBB42.2 Q8$CBB49/CBB42.1 Q9$CBB49/CBB42.2 R2$CBB49/CBB42.2 | length 329.2
  Top Layer w7.9: Q9$CBB49/CBB42.2@10067.1,6209.3 Q8$CBB49/CBB42.1@10117.3,6209.3 10154.7,6171.9 10154.7,6042.2 C3$CBB49/CBB42.2@10146.2,6033.7 ; R2$CBB49/CBB42.2@10146.7,5993.7 10146.7,6033.2 C3$CBB49/CBB42.2@10146.2,6033.7 ; C4$CBB49/CBB42.2@10189.7,6035.3 10188.1,6033.7 C3$CBB49/CBB42.2@10146.2,6033.7
$1I15\$1I44\$2N1: C1$CBB49/CBB43.2 C2$CBB49/CBB43.2 Q5$CBB49/CBB43.1 Q6$CBB49/CBB43.2 R3$CBB49/CBB43.2 | length 252
  Top Layer w7.9: C2$CBB49/CBB43.2@7446.2,7340.3 7447.7,7338.7 C1$CBB49/CBB43.2@7489.6,7338.7 ; R3$CBB49/CBB43.2@7489.1,7298.7 7489.6,7299.2 C1$CBB49/CBB43.2@7489.6,7338.7 ; Q5$CBB49/CBB43.1@7573.8,7429.3 Q6$CBB49/CBB43.2@7523.6,7429.3 7501.8,7429.3 7489.6,7417.2 C1$CBB49/CBB43.2@7489.6,7338.7
$1I15\$1I44\$2N14: C3$CBB49/CBB43.2 C4$CBB49/CBB43.2 Q8$CBB49/CBB43.1 Q9$CBB49/CBB43.2 R1$CBB49/CBB43.2 | length 329.2
  Top Layer w7.9: Q9$CBB49/CBB43.2@7523.6,7514.3 Q8$CBB49/CBB43.1@7573.8,7514.3 7611.2,7476.9 7611.2,7347.2 C3$CBB49/CBB43.2@7602.7,7338.7 ; R1$CBB49/CBB43.2@7603.2,7298.7 7603.2,7338.2 C3$CBB49/CBB43.2@7602.7,7338.7 ; C4$CBB49/CBB43.2@7646.2,7340.3 7644.6,7338.7 C3$CBB49/CBB43.2@7602.7,7338.7
$1I15\$1I45\$2N1: C1$CBB49/CBB44.2 C2$CBB49/CBB44.2 Q5$CBB49/CBB44.1 Q6$CBB49/CBB44.2 R3$CBB49/CBB44.2 | length 252
  Top Layer w7.9: C2$CBB49/CBB44.2@7954.9,7340.3 7956.4,7338.7 C1$CBB49/CBB44.2@7998.3,7338.7 ; R3$CBB49/CBB44.2@7997.8,7298.7 7998.3,7299.2 C1$CBB49/CBB44.2@7998.3,7338.7 ; Q5$CBB49/CBB44.1@8082.5,7429.3 Q6$CBB49/CBB44.2@8032.3,7429.3 8010.5,7429.3 7998.3,7417.2 C1$CBB49/CBB44.2@7998.3,7338.7
$1I15\$1I45\$2N14: C3$CBB49/CBB44.2 C4$CBB49/CBB44.2 Q8$CBB49/CBB44.1 Q9$CBB49/CBB44.2 R1$CBB49/CBB44.2 | length 329.2
  Top Layer w7.9: Q9$CBB49/CBB44.2@8032.3,7514.3 Q8$CBB49/CBB44.1@8082.5,7514.3 8119.9,7476.9 8119.9,7347.2 C3$CBB49/CBB44.2@8111.4,7338.7 ; R1$CBB49/CBB44.2@8111.9,7298.7 8111.9,7338.2 C3$CBB49/CBB44.2@8111.4,7338.7 ; C4$CBB49/CBB44.2@8154.9,7340.3 8153.3,7338.7 C3$CBB49/CBB44.2@8111.4,7338.7
$1I15\$1I46\$2N1: C1$CBB49/CBB45.2 C2$CBB49/CBB45.2 Q5$CBB49/CBB45.1 Q6$CBB49/CBB45.2 R3$CBB49/CBB45.2 | length 252
  Top Layer w7.9: C2$CBB49/CBB45.2@8463.6,7340.3 8465.1,7338.7 C1$CBB49/CBB45.2@8507,7338.7 ; R3$CBB49/CBB45.2@8506.5,7298.7 8507,7299.2 C1$CBB49/CBB45.2@8507,7338.7 ; Q5$CBB49/CBB45.1@8591.2,7429.3 Q6$CBB49/CBB45.2@8541,7429.3 8519.2,7429.3 8507,7417.2 C1$CBB49/CBB45.2@8507,7338.7
$1I15\$1I46\$2N14: C3$CBB49/CBB45.2 C4$CBB49/CBB45.2 Q8$CBB49/CBB45.1 Q9$CBB49/CBB45.2 R1$CBB49/CBB45.2 | length 329.2
  Top Layer w7.9: Q9$CBB49/CBB45.2@8541,7514.3 Q8$CBB49/CBB45.1@8591.2,7514.3 8628.6,7476.9 8628.6,7347.2 C3$CBB49/CBB45.2@8620.1,7338.7 ; R1$CBB49/CBB45.2@8620.6,7298.7 8620.6,7338.2 C3$CBB49/CBB45.2@8620.1,7338.7 ; C4$CBB49/CBB45.2@8663.6,7340.3 8662,7338.7 C3$CBB49/CBB45.2@8620.1,7338.7
$1I15\$1I47\$2N1: C1$CBB49/CBB46.2 C2$CBB49/CBB46.2 Q5$CBB49/CBB46.1 Q6$CBB49/CBB46.2 R3$CBB49/CBB46.2 | length 252
  Top Layer w7.9: C2$CBB49/CBB46.2@8972.3,7340.3 8973.8,7338.7 C1$CBB49/CBB46.2@9015.7,7338.7 ; R3$CBB49/CBB46.2@9015.2,7298.7 9015.7,7299.2 C1$CBB49/CBB46.2@9015.7,7338.7 ; Q5$CBB49/CBB46.1@9099.9,7429.3 Q6$CBB49/CBB46.2@9049.7,7429.3 9027.9,7429.3 9015.7,7417.2 C1$CBB49/CBB46.2@9015.7,7338.7
$1I15\$1I47\$2N14: C3$CBB49/CBB46.2 C4$CBB49/CBB46.2 Q8$CBB49/CBB46.1 Q9$CBB49/CBB46.2 R1$CBB49/CBB46.2 | length 329.2
  Top Layer w7.9: Q9$CBB49/CBB46.2@9049.7,7514.3 Q8$CBB49/CBB46.1@9099.9,7514.3 9137.3,7476.9 9137.3,7347.2 C3$CBB49/CBB46.2@9128.8,7338.7 ; R1$CBB49/CBB46.2@9129.3,7298.7 9129.3,7338.2 C3$CBB49/CBB46.2@9128.8,7338.7 ; C4$CBB49/CBB46.2@9172.3,7340.3 9170.7,7338.7 C3$CBB49/CBB46.2@9128.8,7338.7
$1I15\$1I48\$2N1: C1$CBB49/CBB47.2 C2$CBB49/CBB47.2 Q5$CBB49/CBB47.1 Q6$CBB49/CBB47.2 R3$CBB49/CBB47.2 | length 252
  Top Layer w7.9: C2$CBB49/CBB47.2@9481,7340.3 9482.5,7338.7 C1$CBB49/CBB47.2@9524.4,7338.7 ; R3$CBB49/CBB47.2@9523.9,7298.7 9524.4,7299.2 C1$CBB49/CBB47.2@9524.4,7338.7 ; Q5$CBB49/CBB47.1@9608.6,7429.3 Q6$CBB49/CBB47.2@9558.4,7429.3 9536.6,7429.3 9524.4,7417.2 C1$CBB49/CBB47.2@9524.4,7338.7
$1I15\$1I48\$2N14: C3$CBB49/CBB47.2 C4$CBB49/CBB47.2 Q8$CBB49/CBB47.1 Q9$CBB49/CBB47.2 R1$CBB49/CBB47.2 | length 329.2
  Top Layer w7.9: Q9$CBB49/CBB47.2@9558.4,7514.3 Q8$CBB49/CBB47.1@9608.6,7514.3 9646,7476.9 9646,7347.2 C3$CBB49/CBB47.2@9637.5,7338.7 ; R1$CBB49/CBB47.2@9638,7298.7 9638,7338.2 C3$CBB49/CBB47.2@9637.5,7338.7 ; C4$CBB49/CBB47.2@9681,7340.3 9679.4,7338.7 C3$CBB49/CBB47.2@9637.5,7338.7
$1I15\$1I49\$2N1: C1$CBB49/CBB48.2 C2$CBB49/CBB48.2 Q5$CBB49/CBB48.1 Q6$CBB49/CBB48.2 R3$CBB49/CBB48.2 | length 252
  Top Layer w7.9: C2$CBB49/CBB48.2@9989.7,7340.3 9991.2,7338.7 C1$CBB49/CBB48.2@10033.1,7338.7 ; R3$CBB49/CBB48.2@10032.6,7298.7 10033.1,7299.2 C1$CBB49/CBB48.2@10033.1,7338.7 ; Q5$CBB49/CBB48.1@10117.3,7429.3 Q6$CBB49/CBB48.2@10067.1,7429.3 10045.3,7429.3 10033.1,7417.2 C1$CBB49/CBB48.2@10033.1,7338.7
$1I15\$1I49\$2N14: C3$CBB49/CBB48.2 C4$CBB49/CBB48.2 Q8$CBB49/CBB48.1 Q9$CBB49/CBB48.2 R1$CBB49/CBB48.2 | length 329.2
  Top Layer w7.9: Q9$CBB49/CBB48.2@10067.1,7514.3 Q8$CBB49/CBB48.1@10117.3,7514.3 10154.7,7476.9 10154.7,7347.2 C3$CBB49/CBB48.2@10146.2,7338.7 ; R1$CBB49/CBB48.2@10146.7,7298.7 10146.7,7338.2 C3$CBB49/CBB48.2@10146.2,7338.7 ; C4$CBB49/CBB48.2@10189.7,7340.3 10188.1,7338.7 C3$CBB49/CBB48.2@10146.2,7338.7
$1I15\M3_COL+1: Q5$CBB49/CBB1.2 Q5$CBB49/CBB2.2 Q5$CBB49/CBB3.2 Q5$CBB49/CBB4.2 Q5$CBB49/CBB5.2 Q5$CBB49/CBB6.2 Q5$CBB49/CBB37.2 Q5$CBB49/CBB43.2 R3$CBB49.2 U3$CBB49.2 | length 4710
  Top Layer w5.9: R3$CBB49.2@7465.3,5316.3 7465.3,5287.7 v1(7470.4,5282.6)
  Top Layer w7.9: R3$CBB49.2@7465.3,5316.3 7531.8,5316.3 U3$CBB49.2@7537.6,5310.6 ; Q5$CBB49/CBB6.2@7573.8,5808.2 7587.5,5821.9 v1(7587.5,5833.7) ; Q5$CBB49/CBB37.2@7573.8,6073.2 7587.5,6086.9 v1(7587.5,6098.7) ; Q5$CBB49/CBB5.2@7573.8,6593.2 7587.5,6606.9 v1(7587.5,6618.7) ; Q5$CBB49/CBB4.2@7573.8,7113.2 7587.5,7126.9 v1(7587.5,7138.7) ; Q5$CBB49/CBB43.2@7573.8,7378.2 7587.5,7391.9 v1(7587.5,7403.7) ; Q5$CBB49/CBB3.2@7573.8,7898.2 7587.5,7911.9 v1(7587.5,7923.7) ; Q5$CBB49/CBB2.2@7573.8,8683.2 7587.5,8696.9 v1(7587.5,8708.7) ; Q5$CBB49/CBB1.2@7573.8,9203.2 7587.5,9216.9 v1(7587.5,9228.7)
  Inner4 w7.9: v1(7470.4,5282.6) 7510.2,5282.6 7566.2,5338.6 7566.2,5833.5 ; v1(7566.2,9398.7) 7566.2,9228.5 ; v1(7587.5,5833.7) 7566.4,5833.7 7566.2,5833.5 ; v1(7587.5,6098.7) 7566.4,6098.7 7566.2,6098.5 ; v1(7587.5,6618.7) 7566.4,6618.7 7566.2,6618.5 ; v1(7587.5,7138.7) 7566.4,7138.7 7566.2,7138.5 ; v1(7587.5,7403.7) 7566.4,7403.7 7566.2,7403.5 ; v1(7587.5,7923.7) 7566.4,7923.7 7566.2,7923.5 ; v1(7587.5,8708.7) 7566.4,8708.7 7566.2,8708.5 ; v1(7587.5,9228.7) 7566.4,9228.7 7566.2,9228.5 ; 7566.2,5833.5 7566.2,6098.5 ; 7566.2,6098.5 7566.2,6618.5 ; 7566.2,6618.5 7566.2,7138.5 ; 7566.2,7138.5 7566.2,7403.5 ; 7566.2,7403.5 7566.2,7923.5 ; 7566.2,7923.5 7566.2,8708.5 ; 7566.2,8708.5 7566.2,9228.5
$1I15\M3_COL+2: Q5$CBB49/CBB7.2 Q5$CBB49/CBB8.2 Q5$CBB49/CBB9.2 Q5$CBB49/CBB10.2 Q5$CBB49/CBB11.2 Q5$CBB49/CBB12.2 Q5$CBB49/CBB38.2 Q5$CBB49/CBB44.2 R5$CBB49.2 U3$CBB49.9 | length 5077.3
  Top Layer w7.9: U3$CBB49.9@7755.6,5110.6 7798.7,5110.6 7803.9,5105.4 R5$CBB49.2@7830.3,5105.4 ; Q5$CBB49/CBB12.2@8082.5,5808.2 8096.2,5821.9 v1(8096.2,5833.7) ; Q5$CBB49/CBB38.2@8082.5,6073.2 8096.2,6086.9 v1(8096.2,6098.7) ; Q5$CBB49/CBB11.2@8082.5,6593.2 8096.2,6606.9 v1(8096.2,6618.7) ; Q5$CBB49/CBB10.2@8082.5,7113.2 8096.2,7126.9 v1(8096.2,7138.7) ; Q5$CBB49/CBB44.2@8082.5,7378.2 8096.2,7391.9 v1(8096.2,7403.7) ; Q5$CBB49/CBB9.2@8082.5,7898.2 8096.2,7911.9 v1(8096.2,7923.7) ; Q5$CBB49/CBB8.2@8082.5,8683.2 8096.2,8696.9 v1(8096.2,8708.7) ; Q5$CBB49/CBB7.2@8082.5,9203.2 8096.2,9216.9 v1(8096.2,9228.7)
  Inner2 w7.9: v1(7759.5,5110.2) 7783.6,5134.3 8050.5,5134.3 v1(8074.9,5158.7)
  Inner4 w7.9: v1(8074.9,5158.7) 8077.6,5161.4 8077.6,5291.6 8079.9,5294 8079.9,5368 8074.9,5373 8074.9,5833.5 ; v1(8074.9,9398.7) 8074.9,9228.5 ; v1(8096.2,5833.7) 8075.1,5833.7 8074.9,5833.5 ; v1(8096.2,6098.7) 8075.1,6098.7 8074.9,6098.5 ; v1(8096.2,6618.7) 8075.1,6618.7 8074.9,6618.5 ; v1(8096.2,7138.7) 8075.1,7138.7 8074.9,7138.5 ; v1(8096.2,7403.7) 8075.1,7403.7 8074.9,7403.5 ; v1(8096.2,7923.7) 8075.1,7923.7 8074.9,7923.5 ; v1(8096.2,8708.7) 8075.1,8708.7 8074.9,8708.5 ; v1(8096.2,9228.7) 8075.1,9228.7 8074.9,9228.5 ; 8074.9,5833.5 8074.9,6098.5 ; 8074.9,6098.5 8074.9,6618.5 ; 8074.9,6618.5 8074.9,7138.5 ; 8074.9,7138.5 8074.9,7403.5 ; 8074.9,7403.5 8074.9,7923.5 ; 8074.9,7923.5 8074.9,8708.5 ; 8074.9,8708.5 8074.9,9228.5
  Inner4 w11.8: v1(7759.5,5110.2) v1@7759.8,5110.5
$1I15\M3_COL+3: Q5$CBB49/CBB13.2 Q5$CBB49/CBB14.2 Q5$CBB49/CBB15.2 Q5$CBB49/CBB16.2 Q5$CBB49/CBB17.2 Q5$CBB49/CBB18.2 Q5$CBB49/CBB39.2 Q5$CBB49/CBB45.2 R7$CBB49.2 U4$CBB49.2 | length 4719
  Top Layer w7.9: R7$CBB49.2@8482.7,5316.3 8549.2,5316.3 U4$CBB49.2@8555,5310.6 ; Q5$CBB49/CBB18.2@8591.2,5808.1 8604.9,5821.8 v1(8604.9,5833.7) ; Q5$CBB49/CBB39.2@8591.2,6073.2 8604.9,6086.9 v1(8604.9,6098.7) ; Q5$CBB49/CBB17.2@8591.2,6593.1 8604.9,6606.8 v1(8604.9,6618.7) ; Q5$CBB49/CBB16.2@8591.2,7113.1 8604.9,7126.8 v1(8604.9,7138.7) ; Q5$CBB49/CBB45.2@8591.2,7378.2 8604.9,7391.9 v1(8604.9,7403.7) ; Q5$CBB49/CBB15.2@8591.2,7898.1 8604.9,7911.8 v1(8604.9,7923.7) ; Q5$CBB49/CBB14.2@8591.2,8683.1 8604.9,8696.8 v1(8604.9,8708.7) ; Q5$CBB49/CBB13.2@8591.2,9203.1 8604.9,9216.8 v1(8604.9,9228.7)
  Top Layer w11.8: R7$CBB49.2@8482.7,5316.3 8480,5319.1 8456.2,5319.1 8447.9,5327.4 8447.9,5370.9 8480.3,5403.4 v1(8534.5,5403.4)
  Inner4 w7.9: v1(8534.5,5403.4) 8576.6,5403.4 8583.6,5410.4 8583.6,5833.5 ; v1(8583.6,9398.7) 8583.6,9228.5 ; v1(8604.9,5833.7) 8583.8,5833.7 8583.6,5833.5 ; v1(8604.9,6098.7) 8583.8,6098.7 8583.6,6098.5 ; v1(8604.9,6618.7) 8583.8,6618.7 8583.6,6618.5 ; v1(8604.9,7138.7) 8583.8,7138.7 8583.6,7138.5 ; v1(8604.9,7403.7) 8583.8,7403.7 8583.6,7403.5 ; v1(8604.9,7923.7) 8583.8,7923.7 8583.6,7923.5 ; v1(8604.9,8708.7) 8583.8,8708.7 8583.6,8708.5 ; v1(8604.9,9228.7) 8583.8,9228.7 8583.6,9228.5 ; 8583.6,5833.5 8583.6,6098.5 ; 8583.6,6098.5 8583.6,6618.5 ; 8583.6,6618.5 8583.6,7138.5 ; 8583.6,7138.5 8583.6,7403.5 ; 8583.6,7403.5 8583.6,7923.5 ; 8583.6,7923.5 8583.6,8708.5 ; 8583.6,8708.5 8583.6,9228.5
$1I15\M3_COL+4: Q5$CBB49/CBB19.2 Q5$CBB49/CBB20.2 Q5$CBB49/CBB21.2 Q5$CBB49/CBB22.2 Q5$CBB49/CBB23.2 Q5$CBB49/CBB24.2 Q5$CBB49/CBB40.2 Q5$CBB49/CBB46.2 R9$CBB49.2 U4$CBB49.9 | length 5052.5
  Top Layer w7.9: U4$CBB49.9@8773,5110.6 8816.1,5110.6 8821.3,5105.4 R9$CBB49.2@8847.7,5105.4 ; Q5$CBB49/CBB24.2@9099.9,5808.2 9113.6,5821.9 v1(9113.6,5833.7) ; Q5$CBB49/CBB40.2@9099.9,6073.2 9113.6,6086.9 v1(9113.6,6098.7) ; Q5$CBB49/CBB23.2@9099.9,6593.2 9113.6,6606.9 v1(9113.6,6618.7) ; Q5$CBB49/CBB22.2@9099.9,7113.2 9113.6,7126.9 v1(9113.6,7138.7) ; Q5$CBB49/CBB46.2@9099.9,7378.2 9113.6,7391.9 v1(9113.6,7403.7) ; Q5$CBB49/CBB21.2@9099.9,7898.2 9113.6,7911.9 v1(9113.6,7923.7) ; Q5$CBB49/CBB20.2@9099.9,8683.2 9113.6,8696.9 v1(9113.6,8708.7) ; Q5$CBB49/CBB19.2@9099.9,9203.2 9113.6,9216.9 v1(9113.6,9228.7)
  Top Layer w11.8: R9$CBB49.2@8847.7,5105.4 8851.6,5109.3 v1(8851.6,5134.5)
  Inner2 w7.9: v1(8851.6,5134.5) 8875.8,5158.7 8902.8,5158.7 8927.2,5134.3 9062.7,5134.3 v1(9087.1,5158.7)
  Inner4 w7.9: v1(9087.1,5158.7) 9097.1,5168.7 9097.1,5293.7 9112.1,5308.7 9112.1,5324.6 9112.3,5324.8 9112.3,5353.6 9092.3,5373.6 9092.3,5833.5 ; v1(9092.3,9398.7) 9092.3,9228.5 ; v1(9113.6,5833.7) 9092.5,5833.7 9092.3,5833.5 ; v1(9113.6,6098.7) 9092.5,6098.7 9092.3,6098.5 ; v1(9113.6,6618.7) 9092.5,6618.7 9092.3,6618.5 ; v1(9113.6,7138.7) 9092.5,7138.7 9092.3,7138.5 ; v1(9113.6,7403.7) 9092.5,7403.7 9092.3,7403.5 ; v1(9113.6,7923.7) 9092.5,7923.7 9092.3,7923.5 ; v1(9113.6,8708.7) 9092.5,8708.7 9092.3,8708.5 ; v1(9113.6,9228.7) 9092.5,9228.7 9092.3,9228.5 ; 9092.3,5833.5 9092.3,6098.5 ; 9092.3,6098.5 9092.3,6618.5 ; 9092.3,6618.5 9092.3,7138.5 ; 9092.3,7138.5 9092.3,7403.5 ; 9092.3,7403.5 9092.3,7923.5 ; 9092.3,7923.5 9092.3,8708.5 ; 9092.3,8708.5 9092.3,9228.5
$1I15\M3_COL+5: Q5$CBB49/CBB25.2 Q5$CBB49/CBB26.2 Q5$CBB49/CBB27.2 Q5$CBB49/CBB28.2 Q5$CBB49/CBB29.2 Q5$CBB49/CBB30.2 Q5$CBB49/CBB41.2 Q5$CBB49/CBB47.2 R11$CBB49.2 U5$CBB49.2 | length 4690.7
  Top Layer w7.9: R11$CBB49.2@9500.1,5316.3 9566.6,5316.3 U5$CBB49.2@9572.4,5310.6 ; Q5$CBB49/CBB30.2@9608.6,5808.2 9622.3,5821.9 v1(9622.3,5833.7) ; Q5$CBB49/CBB41.2@9608.6,6073.2 9622.3,6086.9 v1(9622.3,6098.7) ; Q5$CBB49/CBB29.2@9608.6,6593.2 9622.3,6606.9 v1(9622.3,6618.7) ; Q5$CBB49/CBB28.2@9608.6,7113.2 9622.3,7126.9 v1(9622.3,7138.7) ; Q5$CBB49/CBB47.2@9608.6,7378.2 9622.3,7391.9 v1(9622.3,7403.7) ; Q5$CBB49/CBB27.2@9608.6,7898.2 9622.3,7911.9 v1(9622.3,7923.7) ; Q5$CBB49/CBB26.2@9608.6,8683.2 9622.3,8696.9 v1(9622.3,8708.7) ; Q5$CBB49/CBB25.2@9608.6,9203.2 9622.3,9216.9 v1(9622.3,9228.7)
  Top Layer w11.8: R11$CBB49.2@9500.1,5316.3 9501.9,5314.6 v1(9501.9,5280.6)
  Inner4 w7.9: v1(9501.9,5280.6) 9601,5379.7 9601,5833.5 ; v1(9601,9398.7) 9601,9228.5 ; v1(9622.3,5833.7) 9601.2,5833.7 9601,5833.5 ; v1(9622.3,6098.7) 9601.2,6098.7 9601,6098.5 ; v1(9622.3,6618.7) 9601.2,6618.7 9601,6618.5 ; v1(9622.3,7138.7) 9601.2,7138.7 9601,7138.5 ; v1(9622.3,7403.7) 9601.2,7403.7 9601,7403.5 ; v1(9622.3,7923.7) 9601.2,7923.7 9601,7923.5 ; v1(9622.3,8708.7) 9601.2,8708.7 9601,8708.5 ; v1(9622.3,9228.7) 9601.2,9228.7 9601,9228.5 ; 9601,5833.5 9601,6098.5 ; 9601,6098.5 9601,6618.5 ; 9601,6618.5 9601,7138.5 ; 9601,7138.5 9601,7403.5 ; 9601,7403.5 9601,7923.5 ; 9601,7923.5 9601,8708.5 ; 9601,8708.5 9601,9228.5
$1I15\M3_COL+6: Q5$CBB49/CBB31.2 Q5$CBB49/CBB32.2 Q5$CBB49/CBB33.2 Q5$CBB49/CBB34.2 Q5$CBB49/CBB35.2 Q5$CBB49/CBB36.2 Q5$CBB49/CBB42.2 Q5$CBB49/CBB48.2 R13$CBB49.2 U5$CBB49.9 | length 5052.3
  Top Layer w7.9: U5$CBB49.9@9790.4,5110.6 9833.5,5110.6 9838.7,5105.4 R13$CBB49.2@9865.1,5105.4 ; Q5$CBB49/CBB36.2@10117.3,5808.2 10131,5821.9 v1(10131,5833.7) ; Q5$CBB49/CBB42.2@10117.3,6073.2 10131,6086.9 v1(10131,6098.7) ; Q5$CBB49/CBB35.2@10117.3,6593.2 10131,6606.9 v1(10131,6618.7) ; Q5$CBB49/CBB34.2@10117.3,7113.2 10131,7126.9 v1(10131,7138.7) ; Q5$CBB49/CBB48.2@10117.3,7378.2 10131,7391.9 v1(10131,7403.7) ; Q5$CBB49/CBB33.2@10117.3,7898.2 10131,7911.9 v1(10131,7923.7) ; Q5$CBB49/CBB32.2@10117.3,8683.2 10131,8696.9 v1(10131,8708.7) ; Q5$CBB49/CBB31.2@10117.3,9203.2 10131,9216.9 v1(10131,9228.7)
  Top Layer w11.8: v1(9856.9,5160.6) 9865.1,5152.4 R13$CBB49.2@9865.1,5105.4
  Inner2 w7.9: v1(9856.9,5160.6) 9895.6,5160.6 9895.6,5166 9906,5176.4 9911.6,5176.4 9911.6,5182 9922,5192.5 9935.8,5192.5 9937.1,5193.7 9987.1,5193.7 9988,5192.8 10002.7,5192.8 10003.7,5193.7 v1(10112.1,5193.7)
  Inner4 w7.9: v1(10109.7,9398.7) 10109.7,9228.5 ; v1(10112.1,5193.7) 10109.7,5196.2 10109.7,5286.3 10127.1,5303.7 10127.1,5383.7 10109.7,5401.2 10109.7,5833.5 ; v1(10131,5833.7) 10109.9,5833.7 10109.7,5833.5 ; v1(10131,6098.7) 10109.9,6098.7 10109.7,6098.5 ; v1(10131,6618.7) 10109.9,6618.7 10109.7,6618.5 ; v1(10131,7138.7) 10109.9,7138.7 10109.7,7138.5 ; v1(10131,7403.7) 10109.9,7403.7 10109.7,7403.5 ; v1(10131,7923.7) 10109.9,7923.7 10109.7,7923.5 ; v1(10131,8708.7) 10109.9,8708.7 10109.7,8708.5 ; v1(10131,9228.7) 10109.9,9228.7 10109.7,9228.5 ; 10109.7,5833.5 10109.7,6098.5 ; 10109.7,6098.5 10109.7,6618.5 ; 10109.7,6618.5 10109.7,7138.5 ; 10109.7,7138.5 10109.7,7403.5 ; 10109.7,7403.5 10109.7,7923.5 ; 10109.7,7923.5 10109.7,8708.5 ; 10109.7,8708.5 10109.7,9228.5
$1I15\M3_COL-1: Q8$CBB49/CBB1.2 Q8$CBB49/CBB2.2 Q8$CBB49/CBB3.2 Q8$CBB49/CBB4.2 Q8$CBB49/CBB5.2 Q8$CBB49/CBB6.2 Q8$CBB49/CBB37.2 Q8$CBB49/CBB43.2 R4$CBB49.2 U3$CBB49.6 | length 4584.5
  Top Layer w7.9: R4$CBB49.2@7465.3,5105.4 7532.4,5105.4 U3$CBB49.6@7537.6,5110.6
  Inner2 w5.9: v1(7536.6,5110.2) v1@7537.3,5111
  Inner4 w7.9: v1(7536.6,5110.2) 7587.1,5160.7 7587.1,5366 7609.9,5388.7 7609.9,5893.5 ; v1(7586.2,5893.7) 7609.6,5893.7 7609.9,5893.5 ; v1(7586.2,6158.7) 7609.6,6158.7 7609.9,6158.5 ; v1(7586.2,6678.7) 7609.6,6678.7 7609.9,6678.5 ; v1(7586.2,7198.7) 7609.6,7198.7 7609.9,7198.5 ; v1(7586.2,7463.7) 7609.6,7463.7 7609.9,7463.5 ; v1(7586.2,7983.7) 7609.6,7983.7 7609.9,7983.5 ; v1(7586.2,8768.7) 7609.6,8768.7 7609.9,8768.5 ; v1(7586.2,9288.7) 7609.6,9288.7 7609.9,9288.5 ; v1(7609.9,9398.7) 7609.9,9288.5 ; 7609.9,5893.5 7609.9,6158.5 ; 7609.9,6158.5 7609.9,6678.5 ; 7609.9,6678.5 7609.9,7198.5 ; 7609.9,7198.5 7609.9,7463.5 ; 7609.9,7463.5 7609.9,7983.5 ; 7609.9,7983.5 7609.9,8768.5 ; 7609.9,8768.5 7609.9,9288.5
$1I15\M3_COL-2: Q8$CBB49/CBB7.2 Q8$CBB49/CBB8.2 Q8$CBB49/CBB9.2 Q8$CBB49/CBB10.2 Q8$CBB49/CBB11.2 Q8$CBB49/CBB12.2 Q8$CBB49/CBB38.2 Q8$CBB49/CBB44.2 R6$CBB49.2 U3$CBB49.13 | length 4780.3
  Top Layer w5.9: R6$CBB49.2@7830.3,5316.3 7835.9,5310.8 v1(7835.9,5237.8)
  Top Layer w7.9: U3$CBB49.13@7755.6,5310.6 7824.5,5310.6 R6$CBB49.2@7830.3,5316.3
  Inner2 w7.9: v1(7835.9,5237.8) 7836.9,5238.7 7846.9,5238.7 7862.8,5222.9 7975.5,5222.9 7991.3,5238.7 8078,5238.7 v1(8106.4,5267.2)
  Inner4 w7.9: v1(8094.9,5893.7) 8118.3,5893.7 8118.6,5893.5 ; v1(8094.9,6158.7) 8118.3,6158.7 8118.6,6158.5 ; v1(8094.9,6678.7) 8118.3,6678.7 8118.6,6678.5 ; v1(8094.9,7198.7) 8118.3,7198.7 8118.6,7198.5 ; v1(8094.9,7463.7) 8118.3,7463.7 8118.6,7463.5 ; v1(8094.9,7983.7) 8118.3,7983.7 8118.6,7983.5 ; v1(8094.9,8768.7) 8118.3,8768.7 8118.6,8768.5 ; v1(8094.9,9288.7) 8118.3,9288.7 8118.6,9288.5 ; v1(8106.4,5267.2) 8118.6,5279.3 8118.6,5893.5 ; v1(8118.6,9398.7) 8118.6,9288.5 ; 8118.6,5893.5 8118.6,6678.5 ; 8118.6,6678.5 8118.6,7198.5 ; 8118.6,7198.5 8118.6,7983.5 ; 8118.6,7983.5 8118.6,8768.5 ; 8118.6,8768.5 8118.6,9288.5
$1I15\M3_COL-3: Q8$CBB49/CBB13.2 Q8$CBB49/CBB14.2 Q8$CBB49/CBB15.2 Q8$CBB49/CBB16.2 Q8$CBB49/CBB17.2 Q8$CBB49/CBB18.2 Q8$CBB49/CBB39.2 Q8$CBB49/CBB45.2 R8$CBB49.2 U4$CBB49.6 | length 4622
  Top Layer w7.9: R8$CBB49.2@8482.7,5105.4 8549.8,5105.4 U4$CBB49.6@8555,5110.6
  Top Layer w11.8: U4$CBB49.6@8555,5110.6 8597.1,5110.6 v1(8614.8,5128.3)
  Inner4 w7.9: v1(8603.6,5893.7) 8627,5893.7 8627.3,5893.4 ; v1(8603.6,6158.7) 8627,6158.7 8627.3,6158.5 ; v1(8603.6,6678.7) 8627,6678.7 8627.3,6678.4 ; v1(8603.6,7198.7) 8627,7198.7 8627.3,7198.4 ; v1(8603.6,7463.7) 8627,7463.7 8627.3,7463.5 ; v1(8603.6,7983.7) 8627,7983.7 8627.3,7983.4 ; v1(8603.6,8768.7) 8627,8768.7 8627.3,8768.4 ; v1(8603.6,9288.7) 8627,9288.7 8627.3,9288.4 ; v1(8614.8,5128.3) 8614.8,5236.5 8627.3,5248.9 8627.3,5336.1 8610.1,5353.2 8610.1,5368 8627.3,5385.1 8627.3,5893.4 ; v1(8627.3,9398.7) 8627.3,9288.4 ; 8627.3,5893.4 8627.3,6158.5 ; 8627.3,6158.5 8627.3,6678.4 ; 8627.3,6678.4 8627.3,7198.4 ; 8627.3,7198.4 8627.3,7463.5 ; 8627.3,7463.5 8627.3,7983.4 ; 8627.3,7983.4 8627.3,8768.4 ; 8627.3,8768.4 8627.3,9288.4
$1I15\M3_COL-4: Q8$CBB49/CBB19.2 Q8$CBB49/CBB20.2 Q8$CBB49/CBB21.2 Q8$CBB49/CBB22.2 Q8$CBB49/CBB23.2 Q8$CBB49/CBB24.2 Q8$CBB49/CBB40.2 Q8$CBB49/CBB46.2 R10$CBB49.2 U4$CBB49.13 | length 4705.9
  Top Layer w7.9: U4$CBB49.13@8773,5310.6 8841.9,5310.6 R10$CBB49.2@8847.7,5316.3
  Top Layer w11.8: R10$CBB49.2@8847.7,5316.3 8847.7,5274.8 v1(8848.7,5273.8)
  Inner2 w7.9: v1(8848.7,5273.8) 8858.6,5283.7 8869,5283.7 8869.6,5284.3 8884.4,5284.3 8885,5283.7 v1(9117.1,5283.7)
  Inner4 w7.9: v1(9112.3,5893.7) 9135.7,5893.7 9136,5893.5 ; v1(9112.3,6158.7) 9135.7,6158.7 9136,6158.5 ; v1(9112.3,6678.7) 9135.7,6678.7 9136,6678.5 ; v1(9112.3,7198.7) 9135.7,7198.7 9136,7198.5 ; v1(9112.3,7463.7) 9135.7,7463.7 9136,7463.5 ; v1(9112.3,7983.7) 9135.7,7983.7 9136,7983.5 ; v1(9112.3,8768.7) 9135.7,8768.7 9136,8768.5 ; v1(9112.3,9288.7) 9135.7,9288.7 9136,9288.5 ; v1(9117.1,5283.7) 9136,5302.6 9136,5893.5 ; v1(9136,9398.7) 9136,9288.5 ; 9136,5893.5 9136,6158.5 ; 9136,6158.5 9136,6678.5 ; 9136,6678.5 9136,7198.5 ; 9136,7198.5 9136,7463.5 ; 9136,7463.5 9136,7983.5 ; 9136,7983.5 9136,8768.5 ; 9136,8768.5 9136,9288.5
$1I15\M3_COL-5: Q8$CBB49/CBB25.2 Q8$CBB49/CBB26.2 Q8$CBB49/CBB27.2 Q8$CBB49/CBB28.2 Q8$CBB49/CBB29.2 Q8$CBB49/CBB30.2 Q8$CBB49/CBB41.2 Q8$CBB49/CBB47.2 R12$CBB49.2 U5$CBB49.6 | length 4649.8
  Top Layer w7.9: R12$CBB49.2@9500.1,5105.4 9567.2,5105.4 U5$CBB49.6@9572.4,5110.6
  Top Layer w11.8: R12$CBB49.2@9500.1,5105.4 9511.9,5117.3 v1(9511.9,5160.6)
  Inner4 w7.9: v1(9511.9,5160.6) 9513.8,5158.7 9562.1,5158.7 9627.1,5223.7 9627.1,5368.7 9644.7,5386.3 9644.7,5893.5 ; v1(9621,5893.7) 9644.4,5893.7 9644.7,5893.5 ; v1(9621,6158.7) 9644.4,6158.7 9644.7,6158.5 ; v1(9621,6678.7) 9644.4,6678.7 9644.7,6678.5 ; v1(9621,7198.7) 9644.4,7198.7 9644.7,7198.5 ; v1(9621,7463.7) 9644.4,7463.7 9644.7,7463.5 ; v1(9621,7983.7) 9644.4,7983.7 9644.7,7983.5 ; v1(9621,8768.7) 9644.4,8768.7 9644.7,8768.5 ; v1(9621,9288.7) 9644.4,9288.7 9644.7,9288.5 ; v1(9644.7,9398.7) 9644.7,9288.5 ; 9644.7,5893.5 9644.7,6158.5 ; 9644.7,6158.5 9644.7,6678.5 ; 9644.7,6678.5 9644.7,7198.5 ; 9644.7,7198.5 9644.7,7463.5 ; 9644.7,7463.5 9644.7,7983.5 ; 9644.7,7983.5 9644.7,8768.5 ; 9644.7,8768.5 9644.7,9288.5
$1I15\M3_COL-6: Q8$CBB49/CBB31.2 Q8$CBB49/CBB32.2 Q8$CBB49/CBB33.2 Q8$CBB49/CBB34.2 Q8$CBB49/CBB35.2 Q8$CBB49/CBB36.2 Q8$CBB49/CBB42.2 Q8$CBB49/CBB48.2 R14$CBB49.2 U5$CBB49.13 | length 4710.7
  Top Layer w7.9: U5$CBB49.13@9790.4,5310.6 R14$CBB49.2@9859.3,5310.6
  Top Layer w11.8: v1(9856.9,5278.7) 9856.9,5308.2 R14$CBB49.2@9865.1,5316.3
  Inner2 w7.9: v1(9856.9,5278.7) 9883.2,5278.7 9887,5282.5 9903.4,5282.5 9905.5,5280.4 v1(10142.1,5280.4)
  Inner4 w7.9: v1(10129.7,5893.7) 10153.1,5893.7 10153.4,5893.5 ; v1(10129.7,6158.7) 10153.1,6158.7 10153.4,6158.5 ; v1(10129.7,6678.7) 10153.1,6678.7 10153.4,6678.5 ; v1(10129.7,7198.7) 10153.1,7198.7 10153.4,7198.5 ; v1(10129.7,7463.7) 10153.1,7463.7 10153.4,7463.5 ; v1(10129.7,7983.7) 10153.1,7983.7 10153.4,7983.5 ; v1(10129.7,8768.7) 10153.1,8768.7 10153.4,8768.5 ; v1(10129.7,9288.7) 10153.1,9288.7 10153.4,9288.5 ; v1(10142.1,5280.4) 10153.4,5291.6 10153.4,5893.5 ; v1(10153.4,9398.7) 10153.4,9288.5 ; 10153.4,5893.5 10153.4,6158.5 ; 10153.4,6158.5 10153.4,6678.5 ; 10153.4,6678.5 10153.4,7198.5 ; 10153.4,7198.5 10153.4,7463.5 ; 10153.4,7463.5 10153.4,7983.5 ; 10153.4,7983.5 10153.4,8768.5 ; 10153.4,8768.5 10153.4,9288.5
$1I17\$1N1: Q3$CBB1.1 Q3$CBB1.3 Q4$CBB1.2 | length 202.4
  Top Layer w7.9: Q4$CBB1.2@7546.5,4456.6 7630.5,4456.6 Q3$CBB1.3@7656.1,4482.2 7672.1,4482.2 7697.7,4456.6 Q3$CBB1.1@7727.7,4456.6
$1I17\$1N2: Q1$CBB1.2 Q4$CBB1.1 Q4$CBB1.3 R10$CBB1.2 | length 253.1
  Top Layer w7.9: R10$CBB1.2@7550.1,4642.2 7532.1,4642.2 7517.1,4627.2 7517.1,4576 Q1$CBB1.2@7546.5,4546.6 Q4$CBB1.1@7546.5,4507.8 7592.6,4507.8 Q4$CBB1.3@7618.2,4482.2
$1I17\$1N3: Q2$CBB1.1 Q2$CBB1.3 Q3$CBB1.2 R2$CBB1.1 R9$CBB1.1 U1$CBB1.6 | length 502.4
  Top Layer w7.9: R2$CBB1.1@7467.1,4734.2 7530.1,4734.2 U1$CBB1.6@7538.1,4742.2 7627.1,4742.2 7705.1,4664.2 R9$CBB1.1@7705.1,4642.2 7705.1,4610.1 Q2$CBB1.3@7667.1,4572.2 ; Q2$CBB1.3@7656.1,4572.2 Q2$CBB1.3@7667.1,4572.2 ; Q3$CBB1.2@7727.7,4507.8 Q2$CBB1.1@7727.7,4546.6 7702.1,4572.2 Q2$CBB1.3@7667.1,4572.2
$1I17\$1N4: Q1$CBB1.1 Q1$CBB1.3 Q2$CBB1.2 | length 372.3
  Top Layer w7.9: Q1$CBB1.1@7546.5,4597.8 7571.5,4597.8 7597.1,4572.2 Q1$CBB1.3@7618.2,4572.2 7618.2,4561.4 7632.1,4547.5 7651.8,4547.5 7713.6,4485.7 7738,4485.7 7752.1,4499.8 7752.1,4573.3 Q2$CBB1.2@7727.7,4597.8
$1I17\$1N9: R1$CBB1.1 R8$CBB1.2 U1$CBB1.1 U1$CBB1.2 U1$CBB1.5 | length 602.5
  Top Layer w7.9: U1$CBB1.5@7538.1,4792.2 7627.1,4792.2 7652.1,4817.2 ; U1$CBB1.1@7538.1,4992.2 U1$CBB1.2@7538.1,4942.2 7592.1,4942.2 7652.1,4882.2 7652.1,4817.2 ; R1$CBB1.1@7827.1,4855.1 R8$CBB1.2@7827.1,4809.2 7819.2,4817.2 7652.1,4817.2
$1I17\$1N13: R4$CBB1.1 R5$CBB1.2 U1$CBB1.3 | length 123.1
  Top Layer w7.9: R5$CBB1.2@7467.1,4960.1 R4$CBB1.1@7467.1,4919.2 7485.1,4919.2 7512.1,4892.2 U1$CBB1.3@7538.1,4892.2
$1I17\$1N14: R3$CBB1.2 R9$CBB1.2 U1$CBB1.8 | length 131.2
  Top Layer w7.9: R9$CBB1.2@7739.2,4642.2 7739.2,4675.2 U1$CBB1.8@7756.1,4692.2 7819.2,4692.2 R3$CBB1.2@7827.1,4700.1
$1I17\$1N15: R3$CBB1.1 R6$CBB1.1 U1$CBB1.9 | length 118.1
  Top Layer w7.9: U1$CBB1.9@7756.1,4742.2 7819.2,4742.2 R3$CBB1.1@7827.1,4734.2 7868,4734.2 R6$CBB1.1@7870.1,4732.2
$1I17\$1N16: R7$CBB1.1 R8$CBB1.1 U1$CBB1.10 | length 122
  Top Layer w7.9: U1$CBB1.10@7756.1,4792.2 7797.1,4792.2 7814.2,4775.1 R8$CBB1.1@7827.1,4775.1 7868,4775.1 R7$CBB1.1@7870.1,4777.2
$1I17\$1N20: R1$CBB1.2 R11$CBB1.2 R12$CBB1.2 U1$CBB1.12 | length 176.5
  Top Layer w7.9: U1$CBB1.12@7756.1,4892.2 7824.2,4892.2 R1$CBB1.2@7827.1,4889.2 7845.1,4889.2 7872.1,4862.2 R12$CBB1.2@7872.1,4854.2 R11$CBB1.2@7912.1,4854.2
$1I17\$1N22: R13$CBB1.2 R14$CBB1.1 U1$CBB1.13 | length 463.6
  Top Layer w7.9: R13$CBB1.2@7659.2,4642.2 7660.6,4643.6 v1(7660.6,4683.6) ; v1(7662.1,4932.2) 7672.1,4942.2 U1$CBB1.13@7756.1,4942.2 7764.1,4950.1 R14$CBB1.1@7827.1,4950.1
  Inner4 w7.9: v1(7660.6,4683.6) 7662.1,4685.1 v1(7662.1,4932.2)
$1I17\SIG_OUT_FULL: R2$CBB1.2 R6$CBB7.2 R10$CBB1.1 R13$CBB1.1 U1$CBB1.7 | length 927.1
  Top Layer w4.7: R6$CBB7.2@6972.1,4940.8 7007.7,4940.8 v1(7008.5,4941.6) ; v1(7342.6,4743.5) 7423.8,4743.5 7447.6,4719.7 7447.6,4719.4 7452.8,4714.1 7453.1,4714.1 R2$CBB1.2@7467.1,4700.1
  Top Layer w7.9: R2$CBB1.2@7467.1,4700.1 7467.2,4700 7484.3,4700 7492.1,4692.2 7572.1,4692.2 7584.2,4680.1 R10$CBB1.1@7584.2,4642.2 R13$CBB1.1@7625.1,4642.2
  Inner2 w4.7: v1(7008.5,4941.6) 7240.6,4941.6 7254.8,4955.8 7277.4,4955.8 7291.7,4941.6 v1(7341.8,4941.6)
  Inner4 w4.7: v1(7341.8,4941.6) 7341.8,4744.3 v1(7342.6,4743.5)
$1I18\$1N1: Q3$CBB2.1 Q3$CBB2.3 Q4$CBB2.2 | length 202.4
  Top Layer w7.9: Q4$CBB2.2@8055.2,4456.6 8139.2,4456.6 Q3$CBB2.3@8164.8,4482.2 8180.8,4482.2 8206.4,4456.6 Q3$CBB2.1@8236.4,4456.6
$1I18\$1N2: Q1$CBB2.2 Q4$CBB2.1 Q4$CBB2.3 R10$CBB2.2 | length 253.1
  Top Layer w7.9: R10$CBB2.2@8058.8,4642.2 8040.8,4642.2 8025.8,4627.2 8025.8,4576 Q1$CBB2.2@8055.2,4546.6 Q4$CBB2.1@8055.2,4507.8 8101.3,4507.8 Q4$CBB2.3@8126.9,4482.2
$1I18\$1N3: Q2$CBB2.1 Q2$CBB2.3 Q3$CBB2.2 R2$CBB2.1 R9$CBB2.1 U1$CBB2.6 | length 502.4
  Top Layer w7.9: R2$CBB2.1@7975.8,4734.2 8038.8,4734.2 U1$CBB2.6@8046.8,4742.2 8135.8,4742.2 8213.8,4664.2 R9$CBB2.1@8213.8,4642.2 8213.8,4610.1 Q2$CBB2.3@8175.8,4572.2 ; Q2$CBB2.3@8164.8,4572.2 Q2$CBB2.3@8175.8,4572.2 ; Q3$CBB2.2@8236.4,4507.8 Q2$CBB2.1@8236.4,4546.6 8210.8,4572.2 Q2$CBB2.3@8175.8,4572.2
